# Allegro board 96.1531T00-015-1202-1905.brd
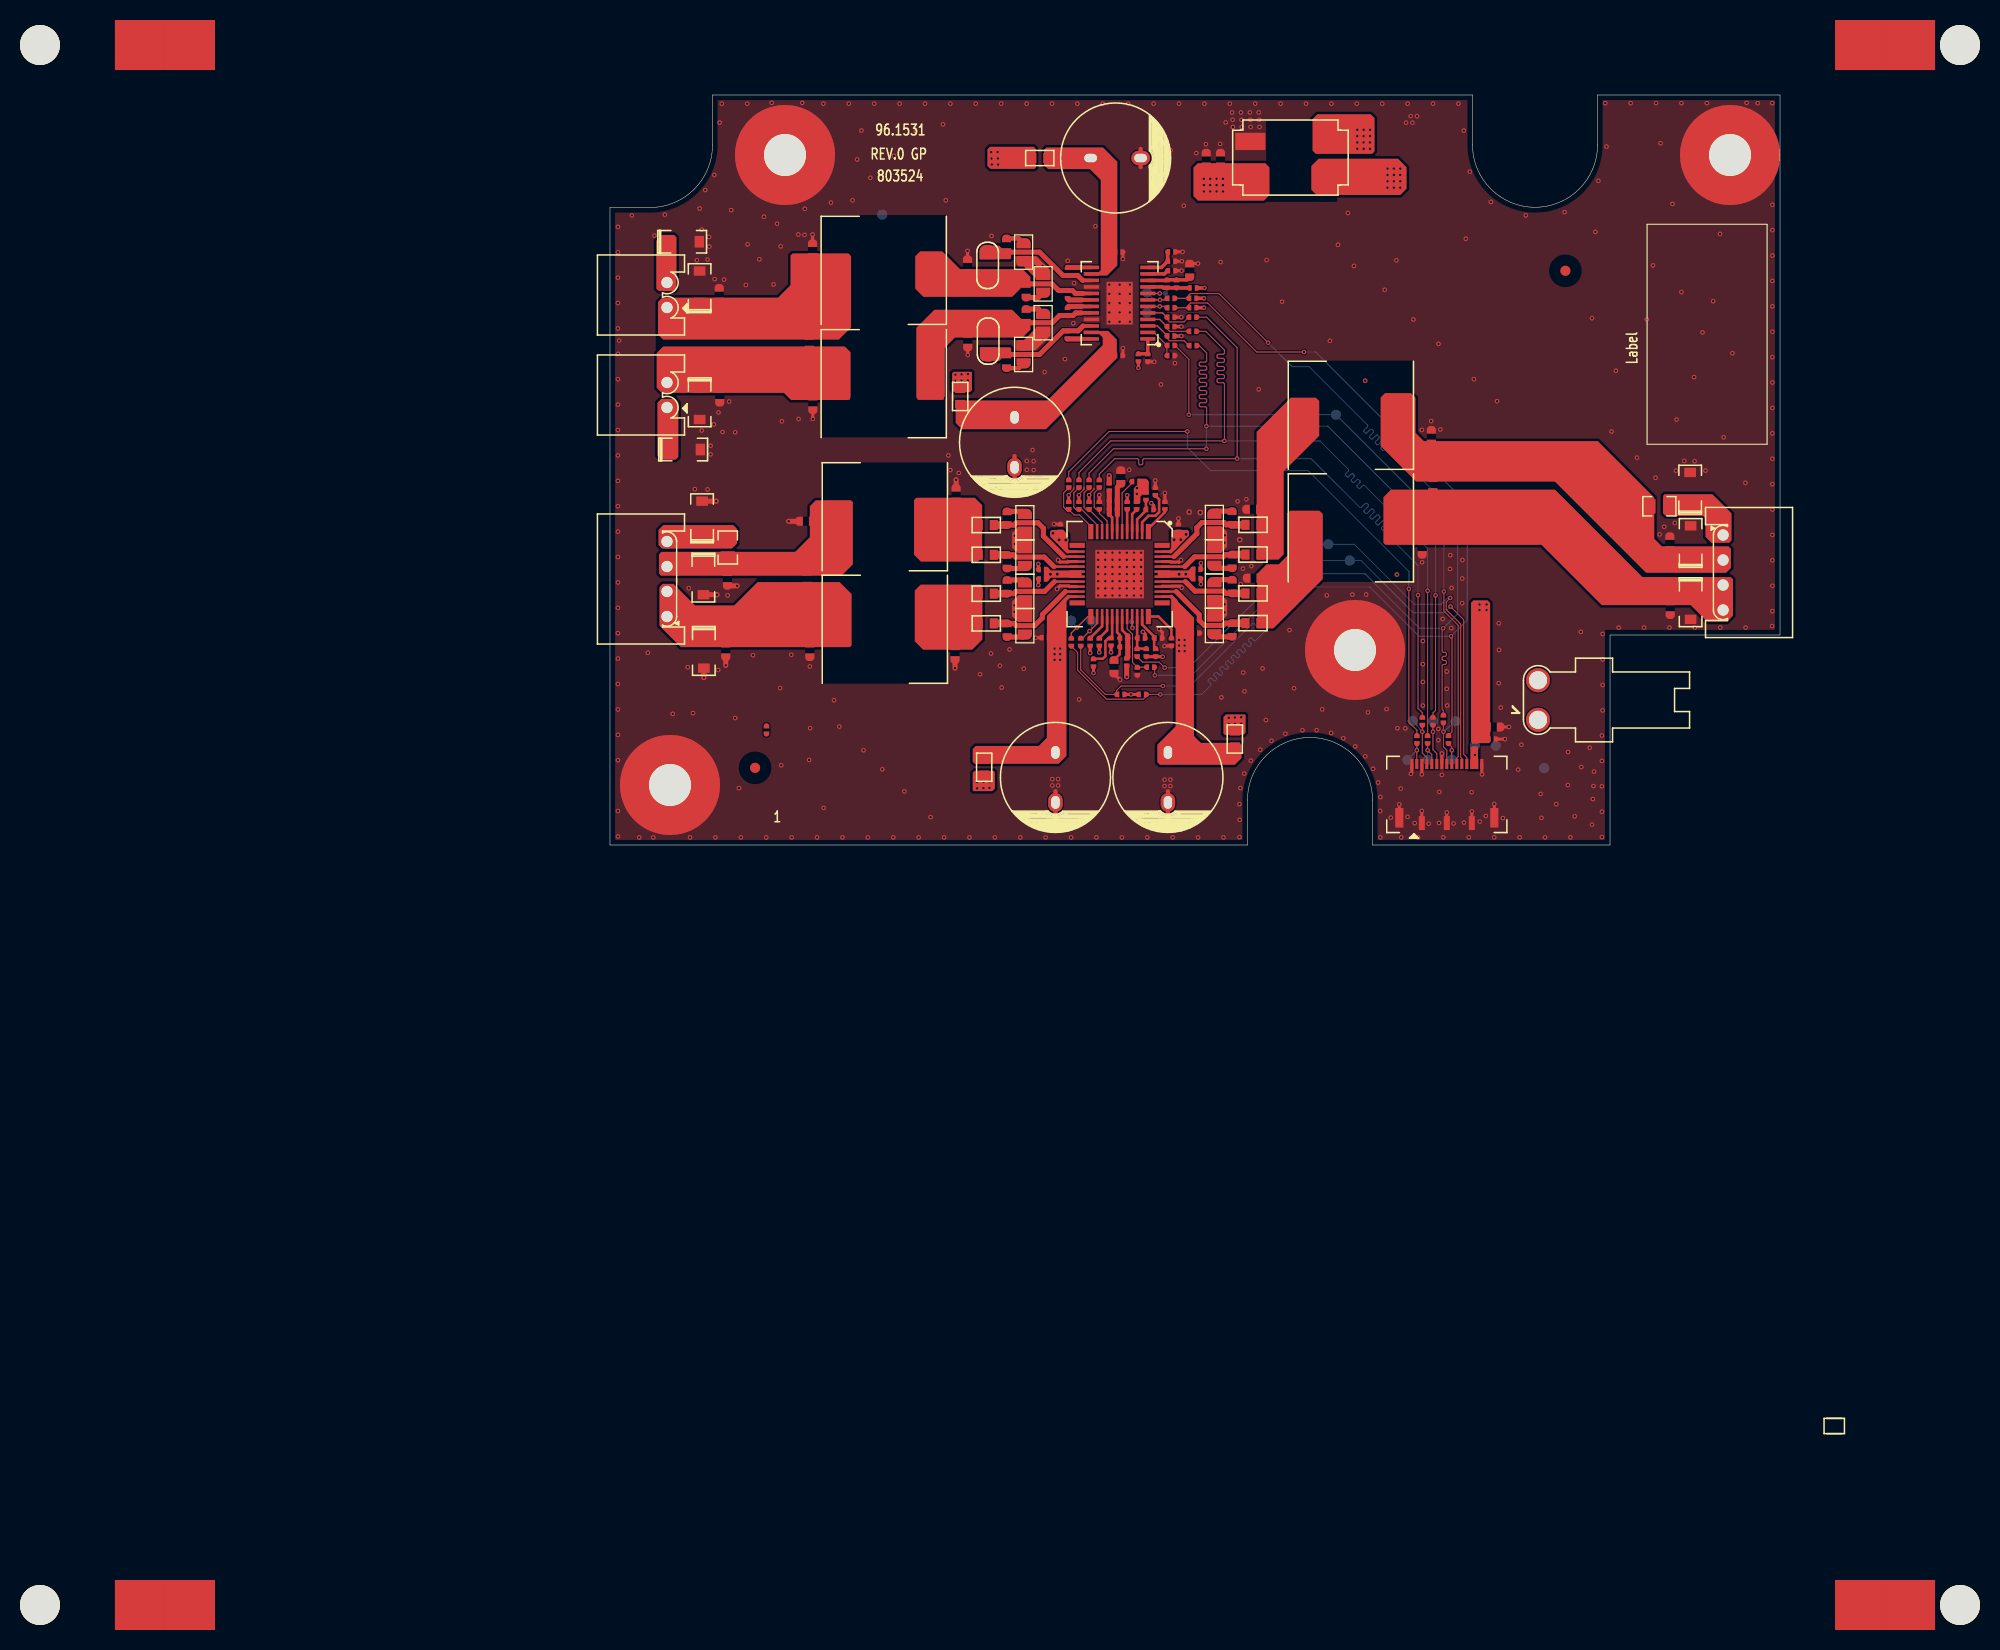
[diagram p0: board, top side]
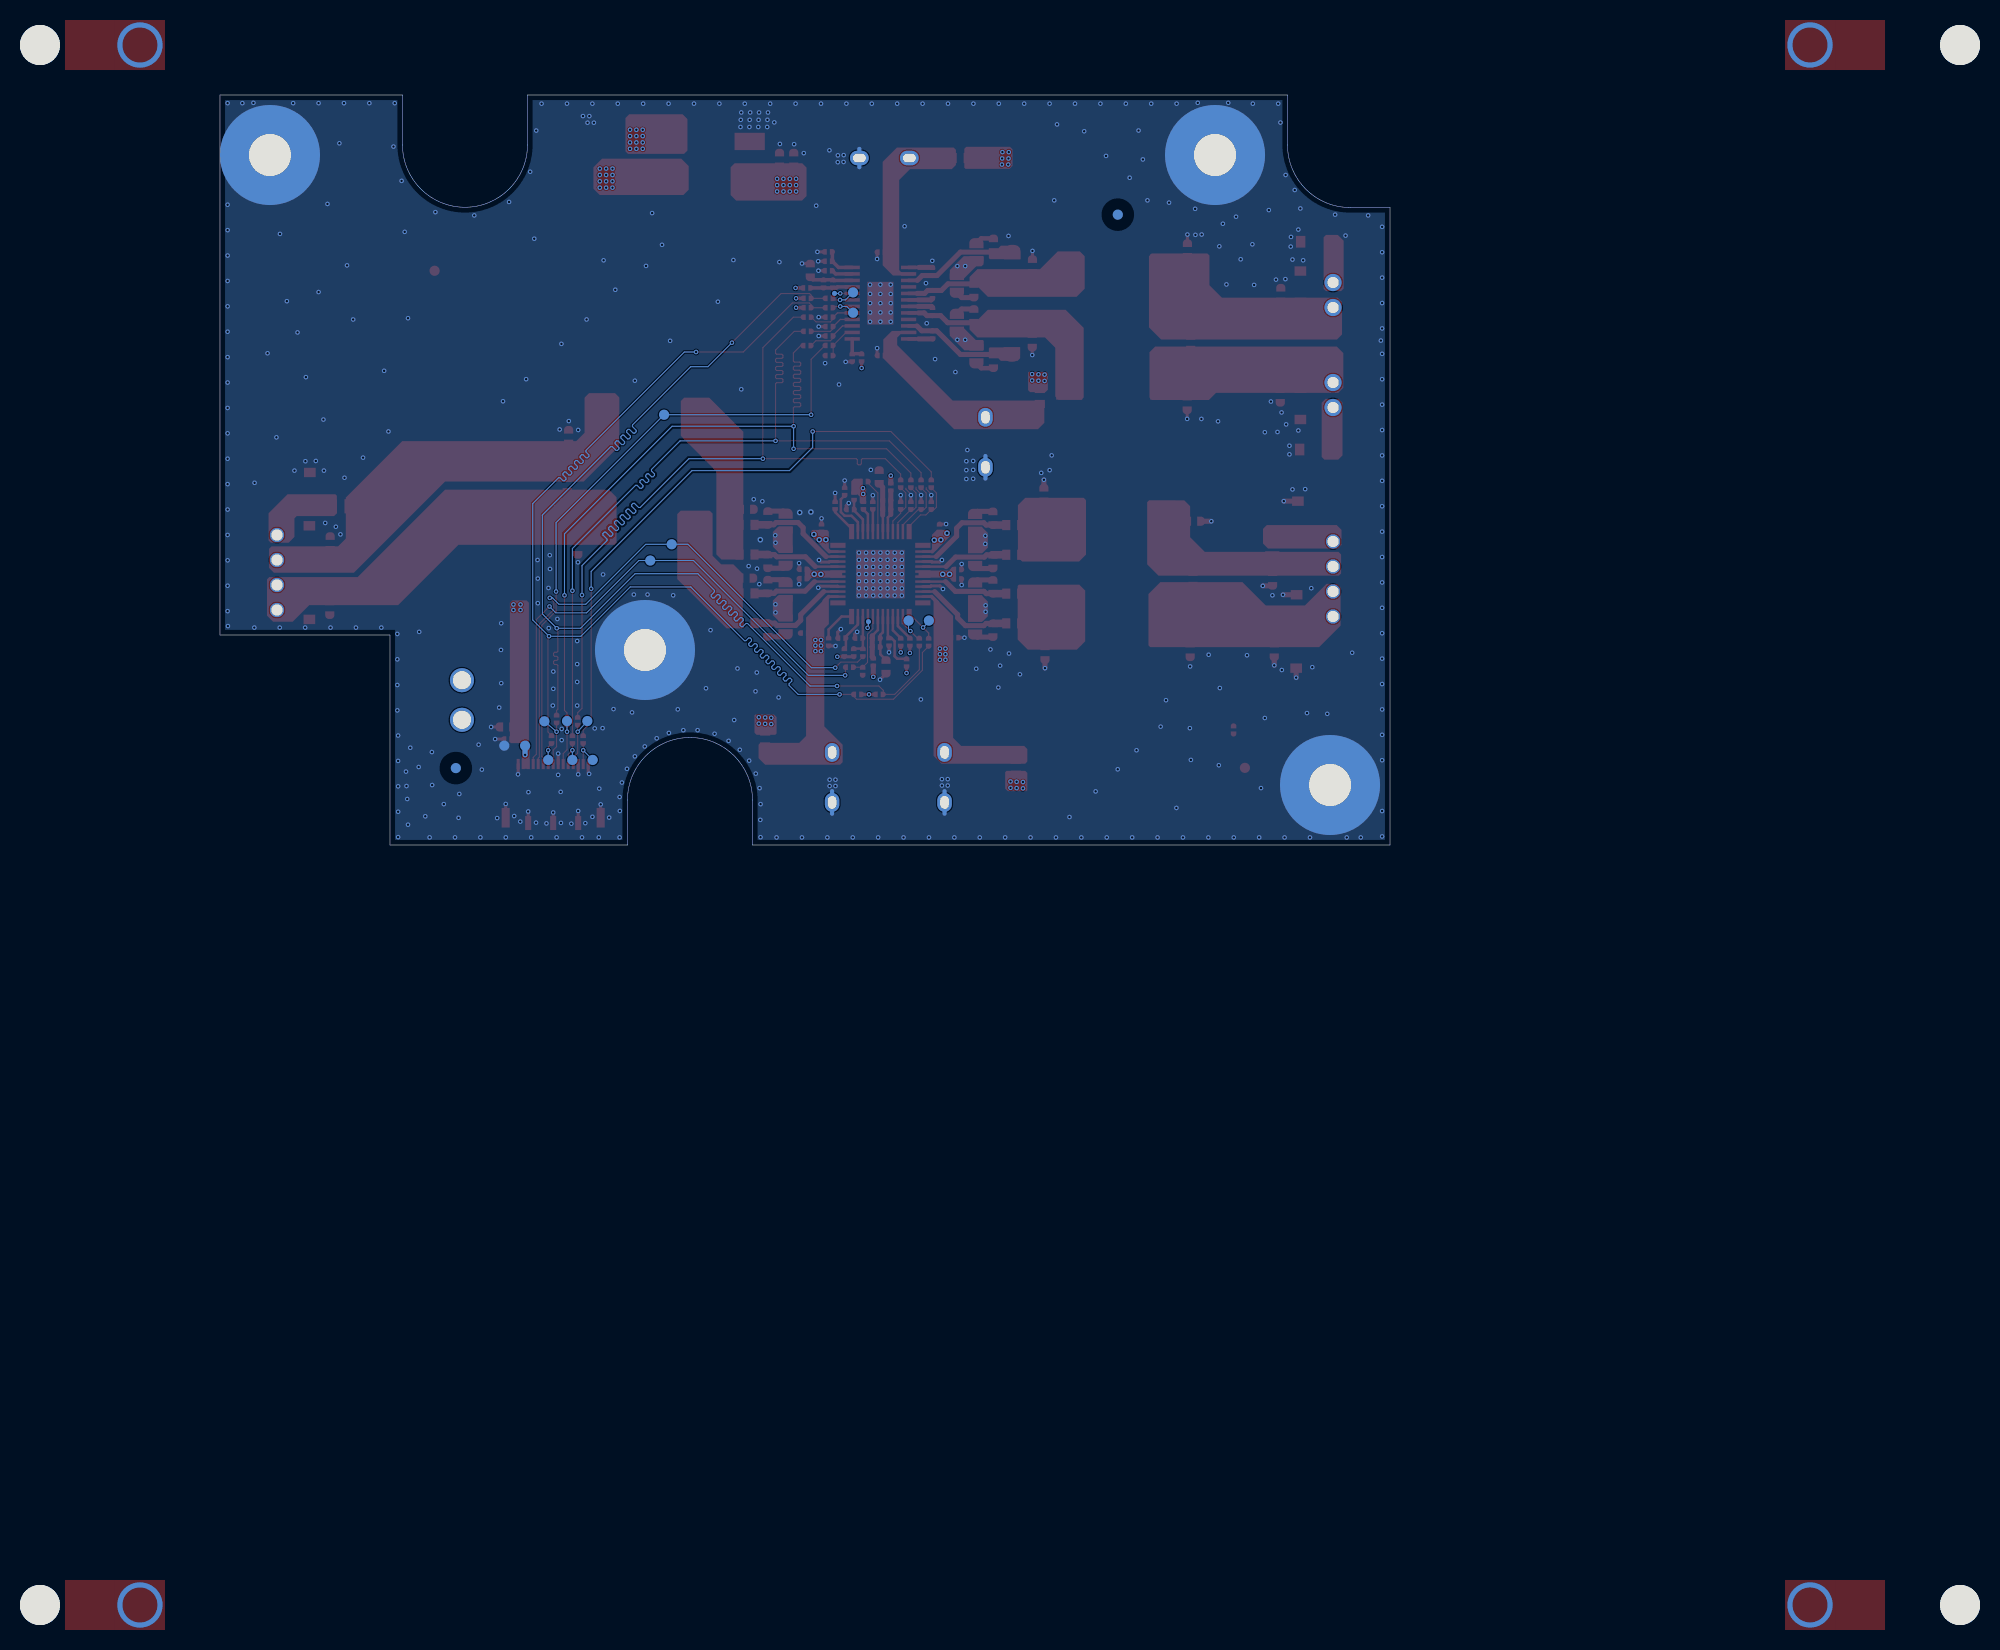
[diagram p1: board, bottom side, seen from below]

Outline 117 x 75 mm; copper layers: TOP, MID1(L2), MID2(L3), BOTTOM. Coordinates in mm from the lower left corner of the outline.
Outline path: 0,63.75 0,0 63.75,0 63.75,4.5 arc(70,10.75) 76.25,4.5 76.25,0 100,0 100,21 117,21 117,75 98.75,75 98.75,70 arc(92.5,63.75) 86.25,70 86.25,75 10.25,75 10.25,70 arc(8.42,65.58) 4,63.75 0,63.75

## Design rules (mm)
net group AD83586B_BCLK: nets AD83586B_BCLK AMP_BCLK BCLK BG5_I2S1_BCLKO
net group AD83586B_DI: nets AD83586B_DI AMP_DI BG5_I2S1_DO DATA
net group AD83586B_LRCK: nets AD83586B_LRCK AMP_LRCK BG5_I2S1_LRCKO LRCK
net group AMP_MSCL: nets AMP_MSCL AMP_SSCL BG5_TW0_SCL SCL
net group AMP_MSDA: nets AMP_MSDA AMP_SSDA BG5_TW0_SDA SDA
net group I2S1: nets BG5_I2S1_MCLK

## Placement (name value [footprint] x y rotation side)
A_D1  SMF36A  [SOD-123G]  7.47 39.55 270 top
A_D2  SMF36A  [SOD-123G]  8.97 44.12 180 top
A_D3  SMF36A  [SOD-123G]  7.37 60.33 270 top
A_D4  SMF36A  [SOD-123G]  8.96 55.83 0 top
A_D5  SMF36A  [SOD-123G]  9.21 32.82 0 top
A_D6  SMF36A  [SOD-123G]  9.34 26.59 180 top
A_D7  SMF36A  [SOD-123G]  9.39 19.25 180 top
A_D8  SMF36A  [SOD-123G]  108.01 35.69 0 top
A_D9  SMF36A  [SOD-123G]  108.06 30.35 0 top
A_D10  SMF36A  [SOD-123G]  108.06 24.13 180 top
BCLK  TP25RD  [ICT040S0]  81.76 8.51 180 bottom
C1218  470pF/50V/X7R/0603  [C-0603S0]  39.66 48.37 180 top
C1219  100nF/50V/X5R  [C-0402S0]  50.88 48.95 270 top
C1220  560uF/35V/DIP  [C-D10_5-5-H22]  40.46 40.27 0 top
C1221  22nF/50V/X7R/0402  [C-0402S0]  45.73 51.02 180 top
C1222  100nF/50V/X7R/0603  [C-0603S0]  20.28 44.16 180 top
C1223  1nF/50V/X7R/0603  [C-0603S0]  10.97 44.91 180 top
C1224  470pF/50V/X7R/0603  [C-0603S0]  41.61 52.91 180 top
C1225  22nF/50V/X7R/0402  [C-0402S0]  45.75 53.35 0 top
C1226  22nF/50V/X7R/0402  [C-0402S0]  45.75 55.05 180 top
C1227  470nF/50V/X7R/0603  [C-0603S0]  19.93 50.23 0 top
C1228  470pF/50V/X7R/0603  [C-0603S0]  41.61 55.43 0 top
C1229  1uF/10V/X5R  [C-0402S0]  55.71 56.11 180 top
C1230  100nF/16V/X5R  [C-0402S0]  56.65 56.11 0 top
C1231  22nF/50V/X7R/0402  [C-0402S0]  45.75 57.35 0 top
C1232  100nF/50V/X7R/0603  [C-0603S0]  20.26 59.5 0 top
C1233  1nF/50V/X7R/0603  [C-0603S0]  10.92 55.04 0 top
C1234  1uF/10V/X5R  [C-0402S0]  56.17 57.43 270 top
C1235  1uF/10V/X5R  [C-0402S0]  56.17 58.37 270 top
C1236  100nF/16V/X5R  [C-0402S0]  56.17 59.32 90 top
C1237  100nF/50V/X5R  [C-0402S0]  50.88 59.29 270 top
C1238  560uF/35V/DIP  [C-D10_5-5-H22]  50.56 68.7 90 top
C1239  470pF/50V/X7R/0603  [C-0603S0]  39.66 59.98 0 top
C1240  1uF/10V/X5R  [C-0402S0]  51.37 19.8 270 top
C1241  100nF/16V/X5R  [C-0402S0]  51.37 20.69 90 top
C1242  470pF/50V/X7R/0603  [C-0603S0]  62.21 21.5 180 top
C1243  470pF/50V/X7R/0603  [C-0603S0]  39.71 21.48 180 top
C1244  560uF/35V/DIP  [C-D10_5-5-H22]  55.79 6.76 0 top
C1245  100nF/50V/X5R  [C-0402S0]  58.56 21.19 270 top
C1246  100nF/50V/X5R  [C-0402S0]  43.52 20.73 90 top
C1247  560uF/35V/DIP  [C-D10_5-5-H22]  44.54 6.76 0 top
C1248  470pF/50V/X7R/0603  [C-0603S0]  39.71 25.82 0 top
C1250  1nF/50V/X7R/0603  [C-0603S0]  106.02 23.67 180 top
C1252  1nF/50V/X7R/0603  [C-0603S0]  11.58 19.46 180 top
C1255  470pF/50V/X7R/0603  [C-0603S0]  62.21 25.85 180 top
C1256  470nF/50V/X7R/0603  [C-0603S0]  19.7 26.62 0 top
C1257  470nF/50V/X7R/0603  [C-0603S0]  82.28 35.99 0 top
C1258  100nF/50V/X5R  [C-0402S0]  58.68 26.63 90 top
C1259  100nF/50V/X5R  [C-0402S0]  43.24 26.61 270 top
C1260  100nF/50V/X5R  [C-0402S0]  58.68 27.57 90 top
C1261  100nF/50V/X5R  [C-0402S0]  43.24 27.55 270 top
C1264  470pF/50V/X7R/0603  [C-0603S0]  62.21 28.36 0 top
C1265  1nF/50V/X7R/0603  [C-0603S0]  105.98 30.21 0 top
C1267  100nF/50V/X5R  [C-0402S0]  56.85 31.69 180 top
C1268  100nF/50V/X5R  [C-0402S0]  45.04 31.69 180 top
C1269  470pF/50V/X7R/0603  [C-0603S0]  39.71 28.34 0 top
C1271  1nF/50V/X7R/0603  [C-0603S0]  11.74 26.6 180 top
C1272  470pF/50V/X7R/0603  [C-0603S0]  39.71 32.68 180 top
C1273  470pF/50V/X7R/0603  [C-0603S0]  62.21 32.7 0 top
C1274  100nF/16V/X5R  [C-0402S0]  50.33 33.57 270 top
C1275  1uF/10V/X5R  [C-0402S0]  50.33 34.46 90 top
C1327  1uF/10V/X5R  [C-0402S0]  53.12 20.69 90 top
C1352  4.7uF/50V/X5R/0805  [C-0805-H1_35]  104.93 33.87 90 top
C1354  4.7uF/50V/X5R/0805  [C-0805-H1_35]  11.78 29.75 0 top
C1357  12pF/50V/NPO  [C-0402S0]  56.09 52.79 270 top
C1358  12pF/50V/NPO  [C-0402S0]  56.09 51.84 270 top
C1359  12pF/50V/NPO  [C-0402S0]  56.09 50.9 270 top
C1360  12pF/50V/NPO  [C-0402S0]  45.87 33.95 180 top
C1361  12pF/50V/NPO  [C-0402S0]  46.89 33.95 180 top
C1362  12pF/50V/NPO  [C-0402S0]  47.91 33.95 180 top
C1363  12pF/50V/NPO  [C-0402S0]  48.93 33.95 180 top
C1380  1uF/50V/0603  [C-0603S0]  59.62 68.56 0 top
C1381  100nF/50V/X7R/0603  [C-0603S0]  61.05 68.56 0 top
C1382  22uF/6.3V/0603  [C-0603S0]  88.38 11.8 90 top
C1383  100nF/16V/X5R  [C-0402S0]  88.21 10.59 90 top
C1384  100nF/50V/X7R/0603  [C-0603S0]  19.59 32.38 90 top
C1385  100nF/50V/X7R/0603  [C-0603S0]  19.98 19.46 180 top
C1386  100nF/50V/X7R/0603  [C-0603S0]  82.13 40.84 0 top
C1387  100nF/50V/X7R/0603  [C-0603S0]  81.21 29.7 180 top
C1388  100nF/50V/X7R/0603  [C-0603S0]  64.29 33.57 90 top
C1389  100nF/50V/X7R/0603  [C-0603S0]  64.34 26.69 90 top
C1390  100nF/50V/X7R/0603  [C-0603S0]  34.61 35.05 0 top
C1391  100nF/50V/X7R/0603  [C-0603S0]  34.5 19.18 180 top
C1392  100nF/50V/X7R/0603  [C-0603S0]  35.75 57.91 0 top
C1393  100nF/50V/X7R/0603  [C-0603S0]  35.77 50.43 180 top
DATA  TP25RD  [ICT040S0]  80.26 12.4 180 bottom
DO  TP25RD  [ICT020]  55.55 55.16 180 bottom
ERROR  TP25RD  [ICT020]  52.15 22.34 0 bottom
FB1  120ohm/3A/0603  [FB-BLM18]  64.3 22.19 90 top
FB2  120ohm/3A/0603  [FB-BLM18]  37.63 22.16 270 top
FB3  120ohm/3A/0603  [FB-BLM18]  37.63 25.13 270 top
FB4  120ohm/3A/0603  [FB-BLM18]  64.3 25.16 90 top
FB5  120ohm/3A/0603  [FB-BLM18]  64.3 29.05 90 top
FB6  120ohm/3A/0603  [FB-BLM18]  37.63 29.02 270 top
FB7  120ohm/3A/0603  [FB-BLM18]  37.63 31.99 270 top
FB8  120ohm/3A/0603  [FB-BLM18]  64.3 32.02 90 top
FID1  NI/FIDUCIAL-MARK  [FIDMS1]  95.54 57.42 0 top
FID2  NI/FIDUCIAL-MARK  [FIDMS1]  14.51 7.72 0 top
FID3  NI/FIDUCIAL-MARK  [FIDMS1]  27.22 63.04 180 bottom
FID4  NI/FIDUCIAL-MARK  [FIDMS1]  93.41 7.69 180 bottom
GND  TP25RD  [ICT040S0]  88.57 9.93 180 bottom
H5  TOOLING HOLE-D=3.2/7mm-PTH  [MPTH165R394I177]  17.5 69 0 top
H6  TOOLING HOLE-D=3.2/7mm-PTH  [MPTH165R394I177]  6 6 0 top
H7  TOOLING HOLE-D=3.2/7mm-PTH  [MPTH165R394I177]  74.5 19.5 0 top
H8  TOOLING HOLE-D=3.2/7mm-PTH  [MPTH165R394I177]  112 69 0 top
J803  S4B-EH(LF)(SN)  [CN-D4X1-2_5RT]  115 27.25 180 top
J804  S4B-EH(LF)(SN)  [CN-D4X1-2_5RT]  2 26.6 0 top
J805  S2B-EH(LF)(SN)  [CN-D2X1-2_5RT]  2 55 0 top
J806  S2B-EH(LF)(SN)  [CN-D2X1-2_5RT]  2 45 0 top
J812  51318-0023L-001  [CN-D2X1-3_96CHD]  98.4 14.5 180 top
J813  502244-1530  [CN-S15X1-0_5A]  83.68 5.07 90 top
L802  120ohm/3A/0603  [FB-BLM18]  35.02 44.85 0 top
L803  10uH/7.8A  [L-S11X10_3-2]  27.38 46.14 90 top
L804  120ohm/1.5A/0402  [L-0402S0]  58.33 55.71 90 top
L805  10uH/7.8A  [L-S11X10_3-2]  27.38 57.46 90 top
L806  120ohm/3A/0603  [FB-BLM18]  42.98 68.7 90 top
L807  120ohm/1.5A/0402  [L-0402S0]  51.67 18.3 0 top
L808  120ohm/3A/0603  [FB-BLM18]  62.48 10.6 180 top
L809  120ohm/3A/0603  [FB-BLM18]  37.42 7.78 180 top
L810  10uH/7.8A  [L-S11X10_3-2]  27.48 21.57 90 top
L811  10uH/7.8A  [L-S11X10_3-2]  74.08 31.72 270 top
L812  10uH/7.8A  [L-S11X10_3-2]  27.48 32.83 90 top
L813  10uH/7.8A  [L-S11X10_3-2]  74.08 42.97 270 top
L814  120ohm/1.5A/0402  [L-0402S0]  49.92 35.8 180 top
L843  1500ohm/3.5A  [L-S9_5X7-4-H7-TEMP]  68.04 68.74 180 top
LRCK  TP25RD  [ICT040S0]  82.3 12.4 180 bottom
MCLK  TP25RD  [ICT040S0]  79.73 8.51 180 bottom
MSCL  TP25RD  [ICT040S0]  53.69 55.26 180 bottom
MSDA  TP25RD  [ICT040S0]  53.69 53.23 180 bottom
NOREF  -  []  111.3 23.5 0 top
NOREF#2  -  []  22.48 37.98 90 top
NOREF#3  -  []  22.68 57.46 0 top
NOREF#4  -  []  49.34 73.8 0 top
NOREF#5  -  []  -62 -71 0 top
NOREF#6  -  []  22.48 26.72 90 top
NOREF#7  -  []  69.08 26.57 0 top
NOREF#8  -  [unnamed#2]  -62 75 270 top
NOREF#9  -  []  -1 32.85 0 top
NOREF#10  -  []  21.98 17.07 90 top
NOREF#11  -  []  47.17 47.94 90 top
NOREF#12  -  []  -20 -16 0 top
NOREF#13  -  []  140 -71 90 top
NOREF#14  -  []  53.34 34.23 0 top
NOREF#15  -  []  68.58 30.22 90 top
NOREF#16  -  []  71.61 -71 90 top
NOREF#17  -  []  61.46 30.59 90 top
NOREF#18  -  []  21.88 52.96 90 top
NOREF#19  -  []  70.84 66.24 0 top
NOREF#20  -  []  69.38 42.97 0 top
NOREF#21  -  []  111.3 26 90 top
NOREF#22  -  []  12.38 62.61 0 top
NOREF#23  -  []  79.08 37.82 90 top
NOREF#24  -  []  0 44.01 0 top
NOREF#25  -  []  63.54 65.24 90 top
NOREF#26  -  []  -1 32.85 0 top
NOREF#27  -  []  0 -14 90 top
NOREF#28  -  []  21.98 28.33 90 top
NOREF#29  -  []  44.36 42.48 0 top
NOREF#30  -  []  63.54 65.24 0 top
NOREF#31  -  []  112 21 0 top
NOREF#32  -  [unnamed#3]  140 -71 270 top
NOREF#33  -  []  22.78 21.57 0 top
NOREF#34  -  []  50.71 22.84 0 top
NOREF#35  -  []  135 -81 90 top
NOREF#36  -  []  46.72 26.84 90 top
NOREF#37  -  []  -62 -41.75 90 top
NOREF#38  -  []  22.38 62.61 90 top
NOREF#39  -  []  135 -81 90 top
NOREF#40  -  []  48.54 22.59 90 top
NOREF#41  -  []  140 -32 90 top
NOREF#42  -  [unnamed#4]  -62 -71 270 top
NOREF#43  -  []  -62 -9.75 90 top
NOREF#44  -  []  48.96 57.39 0 top
NOREF#45  -  []  79.08 26.57 90 top
NOREF#46  -  []  22.68 46.14 0 top
NOREF#47  -  []  22.78 32.83 0 top
NOREF#48  -  []  68.58 41.47 90 top
NOREF#49  -  []  112 21 90 top
NOREF#50  -  []  -62 80 0 top
NOREF#51  -  []  22.38 51.29 90 top
NOREF#52  -  []  122.42 -58.1 0 top
NOREF#53  -  []  54.56 11.86 0 top
NOREF#54  -  []  21.88 41.64 90 top
NOREF#55  -  []  0 -2 0 top
NOREF#56  -  []  12.48 37.98 0 top
NOREF#57  -  []  44.36 42.48 90 top
NOREF#58  -  []  69.08 37.82 0 top
NOREF#59  -  []  54.46 37.59 0 top
NOREF#60  -  []  -62 -71 90 top
NOREF#61  -  []  53.78 53.86 90 top
NOREF#62  -  []  63.29 66.24 0 top
NOREF#63  -  []  63.29 66.24 90 top
NOREF#64  -  []  5 20.35 90 top
NOREF#65  -  []  -62 -41.75 0 top
NOREF#66  -  []  58.1 29.47 90 top
NOREF#67  -  []  -62 5.45 0 top
NOREF#68  -  []  63.75 0 90 top
NOREF#69  -  []  -1 32.85 0 top
NOREF#70  -  []  12.48 26.72 0 top
NOREF#71  -  []  43.32 11.86 0 top
NOREF#72  -  []  5.7 25.35 90 top
NOREF#73  -  []  48.46 24.67 0 top
NOREF#74  -  []  69.38 31.72 0 top
NOREF#75  -  [unnamed#5]  140 75 270 top
NOREF#76  -  []  64.03 67.13 90 top
NOREF#77  -  []  39.23 45.38 0 top
NOREF#78  -  []  12.38 51.29 0 top
NOREF#79  -  []  109.8 21 0 top
NOREF#80  -  []  47.17 47.94 0 top
PD_AD82584F  TP25RD  [ICT040S0]  72.59 43.03 180 bottom
PD_AD83586B  TP25RD  [ICT040S0]  73.97 28.45 180 bottom
R320  4.7K/5%/0402  [R-0402S0]  56.09 48.94 270 top
R2806  0ohm/5%/1206  [R-1206]  37.82 50.39 0 top
R2807  10ohm/5%/0805  [R-0805]  41.36 49.05 0 top
R2808  0ohm/0402  [R-0402S0]  58.27 51.37 90 top
R2809  10ohm/5%/0805  [R-0805]  43.31 52.23 0 top
R2810  0ohm/0402  [R-0402S0]  58.3 49.94 90 top
R2811  0ohm/0402  [R-0402S0]  58.27 52.79 90 top
R2812  0ohm/0402  [R-0402S0]  56.09 53.73 90 top
R2813  0ohm/0402  [R-0402S0]  56.09 54.67 90 top
R2815  10ohm/5%/0805  [R-0805]  43.31 56.11 180 top
R2816  0ohm/0603  [R-0603S0]  57.97 57.46 0 top
R2817  10ohm/5%/0805  [R-0805]  41.36 59.29 180 top
R2818  0ohm/5%/1206  [R-1206]  37.76 57.96 180 top
R2819  0ohm/0603  [R-0603S0]  50.4 17.82 180 top
R2820  10ohm/5%/0805  [R-0805]  60.44 21.96 0 top
R2821  10ohm/5%/0805  [R-0805]  60.44 25.39 0 top
R2822  10ohm/5%/0805  [R-0805]  41.49 21.93 0 top
R2823  10ohm/5%/0805  [R-0805]  41.49 25.36 180 top
R2827  10ohm/5%/0805  [R-0805]  41.49 28.79 180 top
R2829  10ohm/5%/0805  [R-0805]  41.49 32.22 0 top
R2830  10ohm/5%/0805  [R-0805]  60.44 28.82 180 top
R2831  10ohm/5%/0805  [R-0805]  60.44 32.25 180 top
R2832  0ohm/0402  [R-0402S0]  45.87 36.13 180 top
R2833  0ohm/0402  [R-0402S0]  46.89 36.13 180 top
R2834  0ohm/0402  [R-0402S0]  47.91 36.13 180 top
R2835  0ohm/0402  [R-0402S0]  48.93 36.13 180 top
R2837  0ohm/0603  [R-0603S0]  51.08 36.8 0 top
R2886  15K/5%  [R-0402S0]  52.84 48.72 0 top
R2887  15K/5%  [R-0402S0]  53.78 48.72 0 top
R2888  0ohm/0402  [R-0402S0]  56.09 49.96 90 top
R2889  0ohm/0402  [R-0402S0]  47.07 20.28 0 top
R2890  0ohm/0402  [R-0402S0]  46.13 20.28 0 top
R2893  1Mohm  [R-0402S0]  53.63 19.23 180 top
R2894  0ohm/0402  [R-0402S0]  54.82 20.69 90 top
R2895  1K/5%  [R-0402S0]  54.57 19.24 180 top
R2897  1K/5%  [R-0402S0]  48.93 20.28 180 top
R2898  1K/5%  [R-0402S0]  48.01 20.28 180 top
R2899  0ohm/0402  [R-0402S0]  56.14 20.31 0 top
R2901  0ohm/0402  [R-0402S0]  54.53 35.36 180 top
R2902  1K/5%  [R-0402S0]  53.59 34.87 0 top
R2903  1K/5%  [R-0402S0]  52.66 33.95 0 top
R2904  0ohm/0402  [R-0402S0]  51.72 33.95 180 top
R2905  0ohm/0402  [R-0402S0]  55.49 33.95 180 top
R2927  10K/5%  [R-0402S0]  48.35 18.22 180 top
R2928  10K/5%  [R-0402S0]  50.1 20.31 0 top
R2929  0ohm/0402  [R-0402S0]  52.71 19.23 0 top
R2932  10K/5%  [R-0402S0]  58.28 53.73 270 top
R2933  10K/5%  [R-0402S0]  58.28 54.67 270 top
R2968  0ohm/0402  [R-0402S0]  86.48 9.99 0 top
R2970  33/5%/0402  [R-0402S0]  82.3 12.37 0 top
R2971  33/5%/0402  [R-0402S0]  81.76 10.54 0 top
R2972  33/5%/0402  [R-0402S0]  81.23 12.37 0 top
R2974  33/5%/0402  [R-0402S0]  80.69 10.54 0 top
R2976  33/5%/0402  [R-0402S0]  83.85 10.54 0 top
R2977  33/5%/0402  [R-0402S0]  83.34 12.6 0 top
R2980  0ohm/0402  [R-0402S0]  53.98 33.55 90 top
R2981  10K/5%  [R-0402S0]  53.24 15.06 90 top
R2982  10K/5%  [R-0402S0]  51.08 15.06 270 top
R2983  10K/5%  [R-0402S0]  52.58 36.35 90 top
R2984  0ohm/0402  [R-0402S0]  54.05 17.78 90 top
R2985  4.7K/5%/0402  [R-0402S0]  52.73 17.37 180 top
RESET  TP25RD  [ICT040S0]  71.83 30.07 180 bottom
SCL  TP25RD  [ICT040S0]  84.56 12.37 180 bottom
SDA  TP25RD  [ICT040S0]  84.18 8.51 180 bottom
SSCL  TP25RD  [ICT040S0]  48.14 22.44 0 bottom
SSDA  TP25RD  [ICT040S0]  46.11 22.44 0 bottom
U804  AD83586B  [TQFP-48DSH]  50.96 27.09 180 top
U1309  AD82584F  [SSOP-24ESH]  50.96 54.18 0 top
UNK3V3  TP25RD  [ICT040S0]  86.49 9.93 180 bottom
V015  33/5%/0402  [R-0402S0]  15.65 11.51 0 top

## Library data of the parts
A_D1-A_D10 = DIO-TVS-A
BCLK DATA DO ERROR GND LRCK MCLK MSCL MSDA PD_AD82584F PD_AD83586B RESET SCL SDA SSCL SSDA UNK3V3 = TEST_POINT_0
C1218 C1219 C1221-C1228 C1231-C1233 C1237 C1239 C1242 C1243 C1245 C1246 C1248 C1250 C1252 C1255-C1261 C1264 C1265 C1267-C1269 C1271-C1273 C1352 C1354 C1357-C1363 C1380 C1381 C1384-C1393 = CAP
C1220 C1238 C1244 C1247 = CAP AL
C1229 C1234 C1235 C1240 C1275 C1327 = C_0
C1230 C1236 C1241 C1274 C1383 = CAP NP_2
C1382 = CAP NP
FB1-FB8 L802 L804 L806 L807 L809 L814 = BEAD
FID1-FID4 = SCREW-HOLE-1
H5-H8 = TOOLING HOLE-1PIN-NP
J803 J804 = CON4
J805 J806 J812 = CON2X1
J813 = CON15X1-4G_0
L803 L805 L810-L813 = INDUCTOR
L808 = BEAD_0
L843 = CHOKE-4
R320 R2985 = RESISTOR
R2806 R2807 R2809 R2815-R2823 R2827 R2829-R2832 R2837 R2886-R2888 R2893-R2895 R2897-R2899 R2901-R2905 R2927-R2929 R2932 R2933 R2968 R2974 R2980-R2984 V015 = RES
R2808 R2810-R2813 R2833-R2835 R2889 R2890 R2970-R2972 R2976 R2977 = RES: signal model: RES_R-0402S0_0OHM/0402_0ohm/0402
U804 = AD83586B_1
U1309 = AD82584F

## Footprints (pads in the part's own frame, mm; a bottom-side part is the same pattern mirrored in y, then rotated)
C-0402S0
  custom 0.127x0.127 smd: 1(0,-0.406) 2(0,0.406)
C-0603S0
  custom 0.191x0.191 smd: 1(0,-0.686) 2(0,0.686)
C-0805-H1_35
  custom 0.254x0.254 smd: 1(0,-0.889) 2(0,0.889)
C-D10_5-5-H22
  oval 1.448x1.88 hole 0.838x1.27: 1(0,2.5) 2(0,-2.5)
CN-D2X1-2_5RT
  round 1.727 hole 1.118: 1(3.7,-1.25) 2(3.7,1.25)
CN-D2X1-3_96CHD
  round 2.413 hole 1.803: 1(5.6,1.98) 2(5.6,-1.98)
CN-D4X1-2_5RT
  round 1.422 hole 1.118: 1(3.7,-3.75) 2(3.7,-1.25) 3(3.7,1.25) 4(3.7,3.75)
CN-S15X1-0_5A
  rect 1.016x0.305 smd: 1(3.025,3.501) 2(3.025,3.001) 3(3.025,2.501) 4(3.025,2.001) 5(3.025,1.5) 6(3.025,1) 7(3.025,0.5) 8(3.025,0) 9(3.025,-0.5) 10(3.025,-1) 11(3.025,-1.5) 12(3.025,-2.001) 13(3.025,-2.501) 14(3.025,-3.001) 15(3.025,-3.501)
  rect 1.956x0.813 smd: S1(-2.35,4.75) S5(-2.35,-4.75)
  rect 1.397x0.61 smd: S2(-2.879,2.5) S3(-2.879,0) S4(-2.879,-2.5)
FB-BLM18
  rect 1.016x0.813 smd: 1(0,-0.749) 2(0,0.749)
FIDMS1
  round 1.016 smd: 1(0,0)
ICT020
  round 0.508 smd: 1(0,0)
ICT040S0
  round 1.016 smd: 1(0,0)
L-0402S0
  custom 0.127x0.127 smd: 1(0,-0.406) 2(0,0.406)
L-S9_5X7-4-H7-TEMP
  rect 3.023x1.727 smd: 1(4.011,-1.614) 2(4.011,1.614) 3(-4.011,1.614) 4(-4.011,-1.614)
L-S11X10_3-2
  rect 3.2x2.616 smd: 1(0,-4.7) 2(0,4.7)
MPTH165R394I177
  round 10.008 hole 4.191: 1(0,0)
R-0402S0
  custom 0.127x0.127 smd: 1(0,-0.406) 2(0,0.406)
R-0603S0
  custom 0.191x0.191 smd: 1(0,-0.686) 2(0,0.686)
R-0805
  custom 0.254x0.254 smd: 1(0,-0.889) 2(0,0.889)
R-1206
  custom 0.362x0.362 smd: 1(0,-1.333) 2(0,1.333)
SOD-123G
  rect 1.168x0.94 smd: 1(0,-1.568) 2(0,1.568)
SSOP-24ESH
  rect 1.524x0.356 smd: 1(2.819,-3.575) 2(2.819,-2.925) 3(2.819,-2.275) 4(2.819,-1.625) 5(2.819,-0.975) 6(2.819,-0.325) 7(2.819,0.325) 8(2.819,0.975) 9(2.819,1.625) 10(2.819,2.275) 11(2.819,2.925) 12(2.819,3.575) 13(-2.819,3.575) 14(-2.819,2.925) 15(-2.819,2.275) 16(-2.819,1.625) 17(-2.819,0.975) 18(-2.819,0.325) 19(-2.819,-0.325) 20(-2.819,-0.975) 21(-2.819,-1.625) 22(-2.819,-2.275) 23(-2.819,-2.925) 24(-2.819,-3.575)
  rect 2.616x4.267 smd: 25(0,0)
TQFP-48DSH
  rect 0.508x1.524 smd: 1(-2.878,-4.246) 12(2.878,-4.246) 25(2.878,4.246) 36(-2.878,4.246)
  rect 0.254x1.524 smd: 2(-2.25,-4.246) 3(-1.75,-4.246) 4(-1.25,-4.246) 5(-0.75,-4.246) 6(-0.25,-4.246) 7(0.25,-4.246) 8(0.75,-4.246) 9(1.25,-4.246) 10(1.751,-4.246) 11(2.251,-4.246) 26(2.251,4.246) 27(1.751,4.246) 28(1.25,4.246) 29(0.75,4.246) 30(0.25,4.246) 31(-0.25,4.246) 32(-0.75,4.246) 33(-1.25,4.246) 34(-1.75,4.246) 35(-2.25,4.246)
  rect 1.524x0.508 smd: 13(4.246,-2.878) 24(4.246,2.878) 37(-4.246,2.878) 48(-4.246,-2.878)
  rect 1.524x0.254 smd: 14(4.246,-2.25) 15(4.246,-1.75) 16(4.246,-1.25) 17(4.246,-0.75) 18(4.246,-0.25) 19(4.246,0.25) 20(4.246,0.75) 21(4.246,1.25) 22(4.246,1.751) 23(4.246,2.251) 38(-4.246,2.251) 39(-4.246,1.751) 40(-4.246,1.25) 41(-4.246,0.75) 42(-4.246,0.25) 43(-4.246,-0.25) 44(-4.246,-0.75) 45(-4.246,-1.25) 46(-4.246,-1.75) 47(-4.246,-2.25)
  rect 4.851x4.851 smd: 49(0,0)
unnamed#2
  round 1.016 smd: (-5,20) 1(-5,15)
  rect 5.004x5.004 smd: (-5,20) (-5,15)
  round 3.988 hole 3.988 unplated: (-5,5)
unnamed#3
  round 3.988 hole 3.988 unplated: (5,-5)
  rect 5.004x5.004 smd: (5,-10) (5,-15)
  round 1.016 smd: (5,-15.004) 1(5,-10)
unnamed#4
  round 1.016 smd: (5,20) 1(5,15)
  rect 5.004x5.004 smd: (5,20) (5,15)
  round 3.988 hole 3.988 unplated: (5,5)
unnamed#5
  round 3.988 hole 3.988 unplated: (-5,-5)
  rect 5.004x5.004 smd: (-5,-10) (-5,-15)
  round 1.016 smd: (-5,-15) 1(-5,-10)

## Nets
3V3: J813.13 J813.14 R2968.1 UNK3V3.1
GND: A_D1.2 A_D2.2 A_D3.2 A_D4.2 A_D5.2 A_D6.2 A_D7.2 A_D8.2 A_D9.2 A_D10.2 C1219.2 C1220.2(C) C1222.2 C1223.2 C1232.2 C1233.2 C1234.2(B) C1235.2(B) C1236.1 C1237.2 C1238.2(C) C1244.2(C) C1245.2 C1246.2 C1247.2(C) C1250.2 C1252.2 C1258.1 C1259.1 C1260.1 C1261.1 C1265.2 C1267.1 C1268.1 C1271.2 C1327.1(A) C1357.2 C1358.2 C1359.2 C1360.1 C1361.1 C1362.1 C1363.1 C1380.2 C1381.2 C1382.1 C1383.1 C1384.2 C1385.2 C1386.2 C1387.2 C1388.2 C1389.2 C1390.2 C1391.2 C1392.2 C1393.2 GND.1(TP1) H5.1 H6.1 H7.1 H8.1 J813.1 J813.3 J813.7 J813.15 J813.S1 J813.S2 J813.S3 J813.S4 J813.S5 L843.1 R320.2 R2807.2 R2809.1 R2815.1 R2816.2 R2817.2 R2819.2 R2820.2 R2821.1 R2822.2 R2823.2 R2827.1 R2829.1 R2830.1 R2831.2 R2837.2 R2887.1 R2894.1 R2899.1 R2901.1 R2904.1 R2905.1 R2928.1 R2980.1 R2985.2 U804.16(GNDS1) U804.21(GNDS2) U804.40(GNDR) U804.45(GNDL) U804.49(E-PAD) U1309.16(GNDR) U1309.21(GNDL) U1309.25(EPAD)
VDDL: C1219.1 C1220.1(A) L802.1 U1309.23(VDDL)
VDDR: C1237.1 C1238.1(A) L806.1 U1309.14(VDDR)
VDDRA: C1244.1(A) C1245.1 C1258.2 C1260.2 C1267.2 L808.2 U804.38(VDDRA) U804.42(VDDRB) U804.43(VDDLB) U804.47(VDDLA)
VDDSB: C1246.1 C1247.1(A) C1259.2 C1261.2 C1268.2 L809.1 U804.14(VDDSA1) U804.18(VDDSA2) U804.19(VDDSB1) U804.23(VDDSB2)
AD82584_PDN: R320.1 R2888.2 U1309.2(\\P\D\)
AD83586B_BCLK: C1361.2 R2833.2 U804.11(BCLK)
AD83586B_DI: C1363.2 R2835.2 U804.9(SDATA)
AD83586B_LRCK: C1362.2 R2834.2 U804.10(LRCKIN)
AD83586B_MCLK: C1360.2 R2832.2 U804.12(MCLK)
AD83586B_PDN: R2984.2 R2985.1 U804.32(\\P\D\)
AMP_BCLK: C1358.1 R2808.2 U1309.4(BCLK)
AMP_DI: C1357.1 R2811.2 U1309.5(SDATA)
AMP_LRCK: C1359.1 R2810.2 U1309.3(LRCIN)
AMP_MSCL: MSCL.1(TP1) R2813.2 U1309.7(SCL)
AMP_MSDA: MSDA.1(TP1) R2812.2 U1309.6(SDA)
AMP_SSCL: R2889.2 SSCL.1(TP1) U804.26(SCL)
AMP_SSDA: R2890.2 SSDA.1(TP1) U804.25(SDA)
BCLK: BCLK.1(TP1) J813.5 R2971.1
BG5_I2S1_BCLKO: R2808.1 R2833.1 R2971.2
BG5_I2S1_DO: R2811.1 R2835.1 R2972.2
BG5_I2S1_LRCKO: R2810.1 R2834.1 R2970.2
BG5_I2S1_MCLK: R2832.1 R2974.2
BG5_SM_TDO_PCIE_RSTN: J813.11 R2929.1 RESET.1(TP1)
BG5_TW0_SCL: R2813.1 R2889.1 R2933.1 R2977.2 R2982.1
BG5_TW0_SDA: R2812.1 R2890.1 R2932.1 R2976.2 R2981.1
BST_LA: C1221.2 U1309.24(BST_LA)
BST_LB: C1225.2 U1309.19(BST_LB)
BST_RA: C1226.2 U1309.18(BST_RA)
BST_RB: C1231.2 U1309.13(BST_RB)
DATA: DATA.1(TP1) J813.4 R2972.1
LRCK: J813.6 LRCK.1(TP1) R2970.1
MCLK: J813.2 MCLK.1(TP1) R2974.1
MLA: C1218.1 C1221.1 R2806.1 U1309.22(LA)
MLB: C1224.2 C1225.1 C1393.1 L803.1 R2806.2 U1309.20(LB)
MRA: C1226.1 C1228.2 C1392.1 L805.1 R2818.2 U1309.17(RA)
MRB: C1231.1 C1239.1 R2818.1 U1309.15(RB)
PD_AD82584F: J813.10 PD_AD82584F.1(TP1) R2888.1
PD_AD83586B: J813.12 PD_AD83586B.1(TP1) R2984.1
PWR_3V3: C1382.2 C1383.2 L804.1 L807.1 L814.1 R2886.1 R2893.2 R2895.2 R2897.2 R2898.2 R2902.2 R2903.2 R2927.2 R2932.2 R2933.2 R2968.2 R2981.2 R2982.2 R2983.1
PWR_24V: C1380.1 C1381.1 L802.2 L806.2 L808.1 L809.2 L843.2
SAA: C1272.2 FB7.2 U804.15(S1A)
SAB: C1269.2 FB6.2 U804.17(S1B)
SBA: C1243.1 FB2.2 U804.22(S2A)
SBB: C1248.1 FB3.2 U804.20(S2B)
SCL: J813.8 R2977.1 SCL.1(TP1)
SDA: J813.9 R2976.1 SDA.1(TP1)
SLA: C1273.1 FB8.2 U804.46(LA)
SLB: C1264.2 FB5.2 U804.44(LB)
SRA: C1242.1 FB1.2 U804.39(RA)
SRB: C1255.2 FB4.2 U804.41(RB)
N29687767: C1235.1(A) C1236.2 U1309.12(GVDD)
N29687834: C1234.1(A) U1309.11(VREG)
N29687885: C1229.1(A) C1230.2 R2816.1 U1309.10(DGND)
N29687983: C1229.2(B) C1230.1 L804.2 U1309.9(DVDD)
N29689351: C1218.2 R2807.1
N29689362: C1224.1 R2809.2
N29689929: A_D2.1 A_D3.1 C1222.1 C1223.1 C1227.1 J805.2 J806.2 L803.2
N29690216: C1239.2 R2817.1
N29690226: C1228.1 R2815.2
N29690282: A_D1.1 A_D4.1 C1227.2 C1232.1 C1233.1 J805.1 J806.1 L805.2
N29717066: C1274.2 C1275.1(A) R2837.1 U804.7(DGND1)
N29717079: C1274.1 C1275.2(B) L814.2 U804.8(DVDD1)
N29719018: C1240.1(A) C1241.2 R2819.1 U804.30(DGND2)
N29719032: C1240.2(B) C1241.1 L807.2 U804.31(DVDD2)
N29721028: C1242.2 R2820.1
N29721038: C1255.1 R2821.2
N29721066: C1389.1 FB1.1 FB4.1 L811.1
N29721090: A_D10.1 C1250.1 C1257.1 C1387.1 J803.3 J803.4 L811.2
N29721136: C1273.2 R2831.1
N29721154: C1264.1 R2830.2
N29721182: C1388.1 FB5.1 FB8.1 L813.1
N29721210: A_D9.1 C1257.2 C1265.1 C1352.2 C1386.1 J803.2 L813.2
N29736051: A_D6.1 C1256.2 C1271.1 C1354.1 C1384.1 J804.3 L812.2
N29736075: A_D7.1 C1252.1 C1256.1 C1385.1 J804.1 J804.2 L810.2
N29736891: C1248.2 R2823.1
N29736893: C1269.1 R2827.2
N29738065: C1390.1 FB6.1 FB7.1 L812.1
N29738250: C1391.1 FB2.1 FB3.1 L810.1
N29741676: C1243.2 R2822.1
N29741678: C1272.1 R2829.2
N30395079: R2886.2 R2887.2 U1309.1(\\E\R\R\O\R)
N30395618: ERROR.1(TP1) U804.33(\\E\R\R\O\R\)
N30395650: R2901.2 U804.2(MS)
N30396016: R2983.2 U804.6(CLK_OUT)
N30396076: R2902.1 R2980.2 U804.3(\\P\L\L)
N30396158: R2903.1 U804.4(CFG0)
N30396385: R2904.2 U804.5(CFG1)
N30396687: R2898.1 U804.27(SA0)
N30396767: R2897.1 U804.28(SA1)
N30397460: C1327.2(B) R2893.1 R2929.2 U804.34(\\R\E\S\E\T\)
N30397605: R2905.2 U804.1(SDATA1)
N30398199: R2899.2 U804.36(LINEIN)
N30399203: R2894.2 R2895.1 U804.35(LREX)
N30706789: A_D8.1 C1352.1 J803.1
N30708243: A_D5.1 C1354.2 J804.4
N30748963: R2927.1 R2928.2 U804.29(DEF)
N31274082: J812.2 L843.4
N31338205: J812.1 L843.3
N312711240: DO.1(TP1) U1309.8(SDATAO)

Pads without a net: FID1 1; FID2 1; FID3 1; FID4 1; NOREF#8 1; NOREF#32 1; NOREF#42 1; NOREF#75 1; U804 13 24 37 48; V015 1 2

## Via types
v1: diameter 0.457, hole 0.254, TOP to BOTTOM, 658 vias
v2: diameter 0.559, hole 0.305, TOP to BOTTOM, 13 vias

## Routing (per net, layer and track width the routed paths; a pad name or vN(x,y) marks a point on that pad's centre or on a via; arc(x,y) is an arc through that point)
3V3: length 0.9
  BOTTOM w0.508: v1(86.49,9.02) UNK3V3.1
GND: length 82.8
  TOP w0.102: v1(47.91,34.99) 47.91,35.08 48.41,35.59 48.41,35.69 ; v1(45.87,34.99) 45.87,35.08 46.38,35.59 46.38,35.74 ; 47.4,35.79 47.4,35.59 46.89,35.08 v1(46.89,34.99)
  TOP w0.305: C1358.2 v1(57.13,51.84) ; C1383.1 v1(89.48,10.59) ; J813.1 80.18,7.2 v1(80.09,7.11) ; v1(86.18,3.35) 86.18,3.35 J813.S4 ; R2904.1 v1(51.72,34.97) ; R2894.1 55.23,21.28 v1(54.92,21.59) ; v1(57.1,28.5) 56.9,28.3 56.08,28.3 56.04,28.34 U804.45 ; v1(54.13,34.19) 54.38,33.93 R2980.1 ; R2901.1 v1(54.53,36.45) ; U804.40 55.25,25.88 57.02,25.88 v1(57.18,25.73) ; J813.S5 v1(88.43,4.1) ; C1357.2 v1(57.13,52.79) ; C1236.1 v1(57.26,59.32) ; R2899.1 v1(55.45,19.9) ; v1(87.2,7.06) 87.18,7.08 J813.15 ; v1(83.19,9.14) 83.18,9.14 J813.7 ; J813.3 v1(81.18,7.06) ; C1363.1 v1(48.93,34.99) ; v1(44.81,28.5) 45.01,28.3 45.8,28.3 45.84,28.34 U804.16 ; C1362.1 v1(47.91,34.99) ; C1237.2 v1(51.29,58.6) ; C1259.1 v1(42.83,25.99) ; J813.S1 v1(78.93,4.06) ; R2816.2 v1(58.8,58.15) ; v1(53.29,21.31) 53.52,21.07 C1327.1 ; C1235.2 v1(57.18,58.37) ; C1359.2 v1(57.13,50.9) ; v1(42.83,28.1) C1261.1 ; v1(59.09,26.08) C1258.1 ; v1(42.56,20.73) C1246.2 ; R2819.2 v1(51,16.53) ; R2905.1 v1(55.49,35.2) ; R2887.1 v1(54.43,48.32) ; C1360.1 v1(45.87,34.99) ; v1(56.85,32.66) C1267.1 ; C1222.2 v1(20.28,42.61) ; C1361.1 v1(46.89,34.99) ; C1232.2 v1(20.26,61.05) ; C1393.2 v1(35.77,49) ; v1(51.29,49.68) C1219.2 ; J813.S3 v1(83.68,3.25) ; C1260.1 v1(59.09,28.19) ; C1392.2 v1(35.75,59.41) ; J813.S2 v1(81.18,3.4) ; R2928.1 v1(50.1,19.26) ; v1(44.7,25.6) 45.01,25.91 45.9,25.91 45.97,25.84 U804.21 ; C1268.1 v1(44.39,32.09) ; C1234.2 v1(57.16,57.43) ; C1382.1 v1(89.89,11.8)
  TOP w0.406: 53.06,67.79 C1238.2 53.06,69.62 ; 55.79,3.13 C1244.2 55.79,5.39 ; 40.46,36.64 C1220.2 40.46,38.9 ; 44.54,3.13 C1247.2 44.54,5.39
  TOP w0.508: A_D5.2 v1(10.62,34.38) ; C1390.2 v1(34.61,36.53) ; A_D6.2 v1(10.7,25.03) ; C1252.2 v1(11.58,17.96) ; C1384.2 v1(17.87,32.38) ; C1391.2 v1(34.5,17.69) ; C1271.2 v1(12.72,25.91) ; A_D7.2 v1(9.39,16.74)
  MID1(L2) w0.406: 44.54,3.13 C1247.2 44.54,5.39 ; 53.06,67.79 C1238.2 53.06,69.62 ; 40.46,38.9 C1220.2 40.46,36.64 ; 55.79,3.13 C1244.2 55.79,5.39
  MID2(L3) w0.406: 40.46,36.64 C1220.2 40.46,38.9
  BOTTOM w0.406: 44.54,5.39 C1247.2 44.54,3.13 ; 55.79,3.13 C1244.2 55.79,5.39 ; 53.06,67.79 C1238.2 53.06,69.62 ; 40.46,38.9 C1220.2 40.46,36.64
  vias: v1(0.79,61.82) v1(0.79,59.28) v1(0.79,56.74) v1(0.79,54.2) v1(0.79,51.66) v1(0.79,49.12) v1(0.79,46.58) v1(0.79,44.04) v1(0.79,41.5) v1(0.79,38.96) v1(0.79,36.42) v1(0.79,33.88) v1(0.79,31.34) v1(0.79,28.8) v1(0.79,26.26) v1(0.79,23.72) v1(0.79,21.18) v1(0.79,18.64) v1(0.79,16.1) v1(0.79,13.56) v1(0.79,11.02) v1(0.79,8.48) v1(0.79,3.4) v1(0.79,0.86) v1(0.91,50.44) v1(2.19,62.96) v1(2.93,0.76) v1(3.78,19.23) v1(4.33,0.75) v1(4.45,60.94) v1(5.49,63.04) v1(6.27,13.12) v1(7.77,17.78) v1(7.87,25.68) v1(8.01,0.76) v1(8.31,13.19) v1(8.48,35.59) v1(8.69,58.47) v1(8.97,63.65) v1(9.17,61.54) v1(9.17,41.45) v1(9.53,65.5) v1(9.75,58.55) v1(9.75,35.56) v1(9.91,60.81) v1(9.93,59.84) v1(10.06,39.93) v1(10.06,39.07) v1(10.44,67) v1(10.39,42.06) v1(10.46,56.59) v1(10.55,0.76) v1(10.85,43.26) v1(10.82,17.5) v1(10.96,72.25) v1(11.18,74.14) v1(11.25,41.3) v1(11.4,56.54) v1(11.76,24.97) v1(11.91,44.35) v1(12.12,63.49) v1(12.52,41.27) v1(12.52,12.7) v1(12.9,5.69) v1(13.09,0.76) v1(13.59,56.01) v1(13.72,74.14) v1(13.77,60.07) v1(14.3,18.97) v1(14.94,58.57) v1(15.4,62.83) v1(15.63,0.76) v1(16.18,74.22) v1(16.36,56.06) v1(16.71,62.13) v1(17.02,15.7) v1(17.07,59.87) v1(17.12,7.98) v1(17.2,42.37) v1(18.14,19.02) v1(18.17,0.76) v1(18.84,61.05) v1(18.86,42.61) v1(19.23,74.22) v1(19.49,63.62) v1(19.46,61.02) v1(19.91,8.51) v1(19.99,17.86) v1(20.02,11.68) v1(20.71,0.76) v1(21.34,74.14) v1(21.36,3.71) v1(22.1,64.24) v1(22.4,14.48) v1(22.94,11.84) v1(23.25,0.76) v1(23.88,74.14) v1(24.26,64.47) v1(24.71,68.55) v1(25.15,71.45) v1(25.35,9.47) v1(25.79,0.76) v1(26.04,66.73) v1(26.42,74.14) v1(27.23,7.57) v1(28.33,0.76) v1(28.4,68.91) v1(28.96,74.14) v1(29.44,5.36) v1(30.58,71.37) v1(30.87,0.76) v1(31.5,74.14) v1(32.05,2.79) v1(33.3,72.06) v1(33.41,0.76) v1(33.58,64.47) v1(33.83,38.96) v1(34.04,74.14) v1(34.04,37.49) v1(34.87,37.21) v1(35.95,0.76) v1(36.58,74.14) v1(37.01,17.07) v1(38.1,19.15) v1(38.15,60.91) v1(38.49,0.76) v1(38.99,17.93) v1(39.12,74.14) v1(39.17,15.75) v1(39.95,19.56) v1(40.44,23.96) v1(40.44,23.33) v1(40.47,30.93) v1(40.47,30.11) v1(41.03,0.76) v1(41.38,17.63) v1(41.66,74.14) v1(41.68,38.4) v1(41.68,37.52) v1(41.68,36.63) v1(42.27,39.5) v1(42.37,38.38) v1(42.37,37.49) v1(42.37,36.6) v1(42.48,57.89) v1(42.48,50.53) v1(43.26,57.89) v1(43.26,50.53) v1(43.46,47.29) v1(43.57,0.76) v1(44.2,74.14) v1(44.23,6.58) v1(44.23,5.95) v1(44.81,6.58) v1(44.81,5.95) v1(45.49,48.59) v1(45.77,58.42) v1(46.11,0.76) v1(46.33,52.17) v1(46.41,56.18) v1(46.74,74.14) v1(46.91,14.55) v1(48.54,61.87) v1(48.65,0.76) v1(48.82,29.24) v1(48.82,28.52) v1(48.82,27.81) v1(48.82,27.09) v1(48.82,26.38) v1(48.82,25.66) v1(48.82,24.94) v1(49.28,74.14) v1(49.53,29.24) v1(49.53,28.52) v1(49.53,27.81) v1(49.53,27.09) v1(49.53,26.38) v1(49.53,25.66) v1(49.53,24.94) v1(49.93,56.04) v1(49.93,55.11) v1(49.93,54.18) v1(49.93,53.26) v1(49.93,52.33) v1(50.25,29.24) v1(50.25,28.52) v1(50.25,27.81) v1(50.25,27.09) v1(50.25,26.38) v1(50.25,25.66) v1(50.25,24.94) v1(50.96,56.04) v1(50.96,55.11) v1(50.96,54.18) v1(50.96,53.26) v1(50.96,52.33) v1(50.96,29.24) v1(50.96,28.52) v1(50.96,27.81) v1(50.96,27.09) v1(50.96,26.38) v1(50.96,25.66) v1(50.96,24.94) v1(51.19,0.76) v1(51.68,29.24) v1(51.68,28.52) v1(51.68,27.81) v1(51.68,27.09) v1(51.68,26.38) v1(51.68,25.66) v1(51.68,24.94) v1(51.82,74.14) v1(51.92,37.52) v1(51.99,56.04) v1(51.99,55.11) v1(51.99,54.18) v1(51.99,53.26) v1(51.99,52.33) v1(52.39,29.24) v1(52.39,28.52) v1(52.39,27.81) v1(52.39,27.09) v1(52.39,26.38) v1(52.39,25.66) v1(52.39,24.94) v1(53.11,29.24) v1(53.11,28.52) v1(53.11,27.81) v1(53.11,27.09) v1(53.11,26.38) v1(53.11,25.66) v1(53.11,24.94) v1(53.73,0.76) v1(54.36,74.14) v1(54.63,68.99) v1(54.64,68.31) v1(55.09,46.05) v1(55.21,68.97) v1(55.23,68.28) v1(55.45,6.53) v1(55.45,5.9) v1(56.04,6.53) v1(56.04,5.9) v1(56.06,69.47) v1(56.27,0.76) v1(56.49,48.18) v1(56.9,74.14) v1(57.38,63.93) v1(58.62,69.19) v1(58.81,0.76) v1(59.44,74.14) v1(59.59,70.08) v1(61.01,70.1) v1(61.06,58.29) v1(61.14,14.76) v1(61.35,0.76) v1(61.45,30.23) v1(61.47,30.97) v1(61.45,24.07) v1(61.45,23.26) v1(61.57,72.26) v1(61.98,74.14) v1(62.2,73.25) v1(62.26,72.52) v1(62.28,71.81) v1(62.76,34.37) v1(62.94,4.09) v1(62.95,0.78) v1(63.04,5.69) v1(62.97,2.51) v1(63.09,73.25) v1(63.14,72.52) v1(63.07,26.09) v1(63.17,71.81) v1(63.3,27.64) v1(63.32,17.25) v1(63.45,15.37) v1(63.42,7.14) v1(63.63,34.57) v1(63.98,73.25) v1(64.03,72.52) v1(64.06,71.81) v1(64.14,27.89) v1(64.08,8.43) v1(64.52,74.14) v1(64.87,73.25) v1(64.92,72.52) v1(64.95,71.81) v1(64.87,45.57) v1(65.02,9.53) v1(65.25,17.65) v1(65.58,12.5) v1(65.66,58.5) v1(66.14,10.41) v1(67.06,74.14) v1(67.21,54.33) v1(67.54,11.13) v1(67.94,21.49) v1(68.4,15.67) v1(69.24,11.48) v1(69.6,74.14) v1(70.66,11.48) v1(71.22,13.56) v1(71.68,24.97) v1(71.98,50.42) v1(72.14,74.14) v1(72.11,11.2) v1(72.8,60.02) v1(73.33,10.67) v1(73.79,63.2) v1(74.24,25.04) v1(74.4,57.91) v1(74.52,9.86) v1(74.68,74.14) v1(75.51,46.43) v1(75.51,8.86) v1(75.62,25.04) v1(75.79,13.26) v1(76.3,7.62) v1(76.81,6.25) v1(77.04,4.8) v1(77.01,3.4) v1(77.04,0.76) v1(77.22,74.14) v1(77.47,55.52) v1(77.65,13.59) v1(78.08,2.74) v1(78.64,58.47) v1(78.69,27.05) v1(78.74,11.68) v1(79.07,5.64) v1(79.12,0.76) v1(79.53,11.66) v1(79.61,72.23) v1(79.76,74.14) v1(79.76,2.82) v1(80.07,72.89) v1(80.24,72.23) v1(80.34,52.55) v1(80.47,2.18) v1(80.7,72.89) v1(80.8,0.76) v1(81.18,41.5) v1(81.2,28.27) v1(81.28,20.4) v1(81.28,18.08) v1(81.28,16.31) v1(81.28,13.94) v1(81.86,2.13) v1(82.12,42.39) v1(82.3,74.14) v1(82.83,11.61) v1(82.83,10.49) v1(82.85,50.11) v1(82.93,5.31) v1(82.91,2.21) v1(83.03,41.55) v1(83.19,7.01) v1(83.26,22.61) v1(83.34,0.76) v1(83.67,17.35) v1(83.67,15.62) v1(83.72,13.94) v1(84.02,28.98) v1(84,27.61) v1(84.12,21.69) v1(84.15,25.7) v1(84.35,2.16) v1(84.84,74.14) v1(85.24,28.5) v1(85.22,26.64) v1(85.22,24.18) v1(85.37,71.44) v1(85.39,2.24) v1(85.57,60.63) v1(85.88,0.76) v1(85.98,67.33) v1(86.16,5.28) v1(86.39,46.58) v1(86.97,2.34) v1(87.58,2.9) v1(88.09,64.31) v1(88.42,0.76) v1(88.7,44.37) v1(88.87,22.17) v1(88.9,19.51) v1(88.87,16.18) v1(89.08,13.74) v1(89.28,2.69) v1(90.82,7.54) v1(90.96,0.76) v1(91.14,10.03) v1(91.57,62.96) v1(93.07,5.11) v1(93.14,2.72) v1(93.5,0.76) v1(94.61,4.09) v1(95.46,63.29) v1(95.81,9.3) v1(95.78,5.99) v1(96.04,0.76) v1(96.47,2.87) v1(97.08,21.31) v1(97.13,7.8) v1(97.97,9.73) v1(98.2,52.68) v1(98.2,2.03) v1(98.35,5.89) v1(98.27,4.6) v1(98.4,7.34) v1(98.53,61.32) v1(98.84,66.41) v1(99.19,10.95) v1(99.19,8.41) v1(99.19,5.87) v1(99.19,3.33) v1(99.19,0.79) v1(99.26,21.11) v1(99.26,18.57) v1(99.26,16) v1(99.26,13.46) v1(99.52,74.19) v1(99.65,69.84) v1(100.15,41.35) v1(100.58,47.42) v1(100.86,21.74) v1(102.06,74.19) v1(102.69,38.73) v1(103.4,21.74) v1(103.68,52.55) v1(104.29,57.96) v1(104.55,36.73) v1(104.6,74.19) v1(104.95,31.06) v1(105.06,70.17) v1(105.41,31.83) v1(105.94,21.74) v1(106.25,64.11) v1(106.48,32.21) v1(106.6,37.44) v1(106.65,42.55) v1(107.14,74.19) v1(107.14,55.3) v1(107.42,38.4) v1(108.41,46.79) v1(108.46,38.38) v1(108.48,21.74) v1(109.25,51.26) v1(109.55,37.44) v1(109.68,74.19) v1(110.31,54.38) v1(111,61.11) v1(111.02,21.74) v1(111.35,40.77) v1(112.24,49.17) v1(113.54,36.22) v1(113.56,21.74) v1(113.65,74.22) v1(114.76,74.19) v1(116.24,74.19) v1(116.24,64.03) v1(116.24,61.49) v1(116.24,58.95) v1(116.24,56.41) v1(116.24,53.87) v1(116.24,51.33) v1(116.24,48.79) v1(116.24,46.25) v1(116.24,43.71) v1(116.24,41.17) v1(116.24,38.63) v1(116.24,36.09) v1(116.24,33.55) v1(116.24,31.01) v1(116.24,28.47) v1(116.24,25.93) v1(116.24,23.39) v1(116.2,21.89) v2(57.91,33.3) v2(59.03,33.25) v2(62.97,30.53)
VDDRA: length 3.2
  TOP w0.254: 56.13,24.84 U804.38 ; 56.06,29.34 U804.47
  TOP w0.381: 56.65,29.94 56.06,29.34 ; 56.57,24.39 56.13,24.84
  vias: v1(56.9,20.5) v1(56.9,19.94) v1(56.9,19.39) v1(57.46,20.5) v1(57.46,19.94) v1(57.46,19.39) v2(56.41,30.53) v2(56.91,27.07) v2(57.07,30.53) v2(57.61,31.06) v2(57.58,27.08)
VDDSB: length 3.2
  TOP w0.254: 45.84,24.84 U804.23 ; U804.14 45.78,29.34
  TOP w0.381: 45.27,24.27 45.84,24.84 ; 45.78,29.34 45.37,29.75
  vias: v1(44.46,19.64) v1(44.46,19.08) v1(44.46,18.52) v1(45.02,19.64) v1(45.02,19.08) v1(45.02,18.52) v2(44.04,27.08) v2(44.3,31.18) v2(44.73,27.08) v2(44.91,30.52) v2(45.57,30.49)
AD82584_PDN: length 3.5
  TOP w0.102: U1309.2 54.38,51.26 R2888.2 R320.1
AD83586B_BCLK: length 5.9
  TOP w0.102: R2833.2 46.38,35.21 46.38,33.77 46.61,33.54 C1361.2 47.18,33.54 48.71,32.01 U804.11
AD83586B_DI: length 5.3
  TOP w0.102: U804.9 49.71,32.4 48.93,33.18 C1363.2 48.64,33.54 48.42,33.77 48.42,35.21 R2835.2
AD83586B_LRCK: length 5.5
  TOP w0.102: R2834.2 47.4,35.21 47.4,33.77 47.62,33.54 C1362.2 49.21,32.24 U804.10
AD83586B_MCLK: length 6.2
  TOP w0.102: R2832.2 45.36,35.21 45.36,33.77 45.6,33.54 C1360.2 46.41,33.01 46.95,33.01 48.08,31.88 U804.12
AD83586B_PDN: length 6.4
  TOP w0.102: R2984.2 R2985.1 52.25,18.26 52.25,21.08 51.71,21.62 U804.32
AMP_BCLK: length 4.7
  TOP w0.102: R2808.2 55.96,51.37 55.68,51.65 C1358.1
  TOP w0.127: C1358.1 54.97,52.56 U1309.4
AMP_DI: length 4.8
  TOP w0.102: R2811.2 57.39,52.31 55.96,52.31 55.68,52.59 C1357.1
  TOP w0.127: C1357.1 55.26,53.21 U1309.5
AMP_LRCK: length 5.1
  TOP w0.102: C1359.1 55.68,50.69 55.95,50.43 57.41,50.43 R2810.2
  TOP w0.127: U1309.3 54.74,51.91 55.68,50.97 C1359.1
AMP_MSCL: length 3.6
  TOP w0.127: R2813.2 55.53,54.51 v1(55,54.51) U1309.7
  BOTTOM w0.102: MSCL.1 54.44,54.51 v1(55,54.51)
AMP_MSDA: length 3.5
  TOP w0.127: R2812.2 55.55,53.86 v1(54.97,53.86) U1309.6
  BOTTOM w0.102: v1(54.97,53.86) 54.32,53.86 MSDA.1
AMP_SSCL: length 4.1
  TOP w0.127: U804.26 48.71,22.15 v1(47.96,21.39) 47.25,20.69 R2889.2
  BOTTOM w0.102: v1(47.96,21.39) 48.14,21.58 SSCL.1
AMP_SSDA: length 4.1
  TOP w0.127: R2890.2 46.13,21.19 v1(46.69,21.75) 47.78,22.84 U804.25
  BOTTOM w0.102: SSDA.1 46.11,22.33 v1(46.69,21.75)
BCLK: length 3.2
  TOP w0.102: J813.5 82.18,9.05 v1(81.76,9.47) R2971.1
  BOTTOM w0.102: BCLK.1 v1(81.76,9.47)
BG5_I2S1_BCLKO: length 80.7
  TOP w0.102: R2833.1 46.89,37.24 50.06,40.41 v1(61.44,40.41) 61.44,46.13 61.34,46.23 60.81,46.23 60.71,46.33 60.71,46.54 60.81,46.64 61.34,46.64 61.44,46.74 61.44,46.94 61.34,47.04 60.81,47.04 60.71,47.14 60.71,47.35 60.81,47.45 61.34,47.45 61.44,47.55 61.44,47.75 61.34,47.86 60.81,47.86 60.71,47.96 60.71,48.16 60.81,48.26 61.34,48.26 61.44,48.36 61.44,48.57 61.34,48.67 60.81,48.67 60.71,48.77 60.71,48.97 60.81,49.08 61.34,49.08 61.44,49.18 61.44,49.5 59.57,51.37 R2808.1 ; R2971.2 v1(81.76,25.43)
  BOTTOM w0.102: v1(61.44,40.41) 70.99,40.41 73.85,37.55 73.85,37.41 73.55,37.11 73.55,36.96 73.7,36.82 73.84,36.82 74.14,37.12 74.28,37.12 74.43,36.98 74.43,36.83 74.13,36.53 74.13,36.39 74.27,36.24 74.41,36.24 74.72,36.55 74.86,36.55 75,36.4 75,36.26 74.7,35.96 74.7,35.81 74.85,35.67 74.99,35.67 75.29,35.97 75.43,35.97 81.76,29.65 v1(81.76,25.43)
BG5_I2S1_DO: length 78.3
  TOP w0.102: R2835.1 48.93,37.09 50.47,38.63 52.76,38.63 52.87,38.53 52.87,38.13 52.97,38.02 53.17,38.02 53.27,38.13 53.27,38.53 53.37,38.63 v1(62.71,38.63) 62.71,49.73 59.66,52.79 R2811.1 ; v1(80.8,24.99) 80.8,13.67 81.23,13.23 R2972.2
  BOTTOM w0.102: v1(80.8,24.99) 80.8,27.94 78.29,30.44 78.29,30.59 78.71,31 78.71,31.15 78.56,31.29 78.42,31.29 78.01,30.87 77.86,30.87 77.72,31.02 77.72,31.16 78.13,31.58 78.13,31.72 77.99,31.87 77.85,31.87 77.43,31.45 77.29,31.45 77.14,31.59 77.14,31.74 77.56,32.15 77.56,32.3 77.41,32.44 77.27,32.44 76.86,32.03 76.71,32.03 76.57,32.17 76.57,32.31 76.98,32.73 76.98,32.87 76.84,33.02 76.7,33.02 76.28,32.6 76.14,32.6 75.99,32.74 75.99,32.89 76.41,33.3 76.41,33.45 76.26,33.59 76.12,33.59 75.71,33.18 75.56,33.18 75.42,33.32 75.42,33.46 75.83,33.88 75.83,34.02 75.69,34.17 75.55,34.17 75.13,33.75 74.99,33.75 70.1,38.63 v1(62.71,38.63)
BG5_I2S1_LRCKO: length 77.5
  TOP w0.102: R2834.1 47.91,37.19 50.34,39.62 v1(59.64,39.62) ; R2810.1 58.92,49.94 59.66,49.2 59.66,48.39 59.56,48.29 59.03,48.29 58.93,48.19 58.93,47.99 59.03,47.89 59.56,47.89 59.66,47.78 59.66,47.58 59.56,47.48 59.03,47.48 58.93,47.38 58.93,47.18 59.03,47.07 59.56,47.07 59.66,46.97 59.66,46.77 59.56,46.67 59.03,46.67 58.93,46.57 58.93,46.36 59.03,46.26 59.56,46.26 59.66,46.16 59.66,45.96 59.56,45.85 59.03,45.85 58.93,45.75 58.93,45.55 59.03,45.45 59.56,45.45 59.66,45.35 59.66,45.14 59.56,45.04 59.03,45.04 58.93,44.94 58.93,44.74 59.03,44.64 59.56,44.64 59.66,44.53 59.66,44.33 59.56,44.23 59.03,44.23 58.93,44.13 58.93,43.92 59.03,43.82 59.56,43.82 59.66,43.72 59.66,41.9 v1(59.64,41.88) ; R2970.2 82.3,13.21 82.55,13.46 v1(82.55,24.97)
  BOTTOM w0.102: v1(59.64,39.62) v1(59.64,41.88) 71.79,41.88 82.55,31.11 v1(82.55,24.97)
BG5_I2S1_MCLK: length 59.9
  TOP w0.102: R2974.2 80.69,11.49 79.88,12.29 v1(79.88,25.63) ; v1(57.73,41.35) 49.91,41.35 45.87,37.31 R2832.1
  BOTTOM w0.102: v1(57.73,41.35) 57.73,39.75 60.05,37.44 69.8,37.44 79.88,27.36 v1(79.88,25.63)
BG5_SM_TDO_PCIE_RSTN: length 57.1
  TOP w0.102: R2929.1 53.25,18.29 54.91,18.29 v1(55.47,17.73) ; J813.11 85.18,8.67 85.06,8.79 85.06,22.1 83.62,23.55 83.62,24.31 v1(84.02,24.71)
  BOTTOM w0.102: v1(55.47,17.73) 57.86,17.73 70.21,30.07 RESET.1 74.42,30.07 80.42,24.08 83.11,24.08 83.74,24.71 v1(84.02,24.71)
BG5_TW0_SCL: length 118.3
  TOP w0.102: v1(55.3,15.9) 51.1,15.9 50.67,15.47 R2982.1 49.53,15.06 47.07,17.52 R2889.1 ; R2813.1 57.87,54.67 R2933.1 57.87,54.98 58.04,55.14 60.89,55.14 v1(65.8,50.23) ; R2977.2 83.34,13.46 83.21,13.59 83.21,17.95 83.31,18.05 83.54,18.05 83.64,18.16 83.64,18.36 83.54,18.46 83.31,18.46 83.21,18.56 83.21,18.77 83.31,18.87 83.54,18.87 83.64,18.97 83.64,19.17 83.54,19.27 83.31,19.27 83.21,19.37 83.21,21.56 v1(83.32,21.68)
  BOTTOM w0.102: v1(65.8,50.23) 68.21,47.83 69.93,47.83 75.76,42 75.76,41.85 75.38,41.47 75.38,41.33 75.53,41.19 75.67,41.19 76.05,41.56 76.19,41.56 76.33,41.42 76.33,41.28 75.96,40.9 75.96,40.76 76.1,40.61 76.24,40.61 76.62,40.99 76.77,40.99 76.91,40.85 76.91,40.7 76.53,40.32 76.53,40.18 76.68,40.04 76.82,40.04 77.2,40.41 77.34,40.41 77.48,40.27 77.48,40.13 77.11,39.75 77.11,39.61 77.25,39.46 77.39,39.46 77.77,39.84 77.92,39.84 84.76,32.99 84.76,23.11 v1(83.32,21.68) 80.94,21.68 75.49,27.13 69.22,27.13 67.55,25.47 67.55,25.32 67.88,25 67.88,24.85 67.74,24.71 67.59,24.71 67.27,25.04 67.12,25.04 66.98,24.89 66.98,24.75 67.31,24.42 67.31,24.28 67.16,24.13 67.02,24.13 66.69,24.46 66.55,24.46 66.4,24.32 66.4,24.17 66.73,23.85 66.73,23.7 66.59,23.56 66.44,23.56 66.12,23.88 65.97,23.88 65.83,23.74 65.83,23.6 66.16,23.27 66.16,23.13 66.01,22.98 65.87,22.98 65.54,23.31 65.4,23.31 65.25,23.17 65.25,23.02 65.58,22.7 65.58,22.55 65.44,22.41 65.29,22.41 64.97,22.73 64.82,22.73 64.68,22.59 64.68,22.45 65,22.12 65,21.98 64.86,21.83 64.72,21.83 64.39,22.16 64.25,22.16 57.99,15.9 v1(55.3,15.9)
BG5_TW0_SDA: length 122.6
  TOP w0.102: v1(55.04,15.06) R2981.1 53.64,14.88 53.34,14.58 49.66,14.58 46.76,17.48 46.76,19.24 R2890.1 ; R2812.1 57.87,53.73 R2932.1 57.87,54.01 58.06,54.2 59.77,54.2 64.67,49.3 v1(69.39,49.3) ; R2976.2 84.2,11.3 84.2,20.78 v1(84.1,20.88)
  BOTTOM w0.102: v1(55.04,15.06) 59.18,15.06 60.09,15.97 60.09,16.12 59.82,16.39 59.82,16.54 59.96,16.68 60.11,16.68 60.38,16.41 60.53,16.41 60.67,16.55 60.67,16.69 60.39,16.97 60.39,17.11 60.54,17.26 60.68,17.26 60.96,16.98 61.1,16.98 61.24,17.12 61.24,17.27 60.97,17.54 60.97,17.69 61.11,17.83 61.26,17.83 61.53,17.56 61.68,17.56 61.82,17.7 61.82,17.84 61.54,18.12 61.54,18.26 61.69,18.41 61.83,18.41 62.11,18.13 62.25,18.13 62.39,18.27 62.39,18.42 62.12,18.69 62.12,18.84 62.26,18.98 62.41,18.98 62.68,18.71 62.83,18.71 62.97,18.85 62.97,18.99 62.69,19.27 62.69,19.41 62.84,19.56 62.98,19.56 63.26,19.28 63.4,19.28 63.54,19.42 63.54,19.57 63.27,19.84 63.27,19.99 63.41,20.13 63.56,20.13 63.83,19.86 63.98,19.86 64.12,20 64.12,20.14 63.84,20.42 63.84,20.56 63.99,20.71 64.13,20.71 64.41,20.43 64.55,20.43 69.93,25.81 75.97,25.81 80.9,20.88 v1(84.1,20.88) 85.72,22.5 85.72,34.14 83.14,36.73 82.99,36.73 82.69,36.43 82.55,36.43 82.4,36.57 82.4,36.71 82.7,37.01 82.7,37.16 82.56,37.3 82.42,37.3 82.12,37 81.97,37 81.83,37.14 81.83,37.29 82.13,37.59 82.13,37.73 81.99,37.88 81.84,37.88 81.54,37.58 81.4,37.58 81.25,37.72 81.25,37.86 81.55,38.16 81.55,38.31 81.41,38.45 81.27,38.45 80.97,38.15 80.82,38.15 80.68,38.3 80.68,38.44 80.98,38.74 80.98,38.88 80.84,39.03 80.69,39.03 80.39,38.73 80.25,38.73 80.1,38.87 80.1,39.01 80.4,39.31 80.4,39.46 70.56,49.3 v1(69.39,49.3)
BST_LA: length 2.4
  TOP w0.356: U1309.24 47.15,50.61
  TOP w0.508: 47.15,50.61 C1221.2
BST_LB: length 2.4
  TOP w0.356: 47.2,53.86 U1309.19
  TOP w0.508: C1225.2 45.86,53.86 47.2,53.86
BST_RA: length 2.4
  TOP w0.356: 47.2,54.51 U1309.18
  TOP w0.508: 47.2,54.51 45.88,54.51 C1226.2
BST_RB: length 2.4
  TOP w0.356: U1309.13 47.1,57.76
  TOP w0.508: 47.1,57.76 C1231.2
DATA: length 5.5
  TOP w0.102: J813.4 81.68,8.75 81.23,9.2 v1(81.23,11.33) R2972.1
  BOTTOM w0.102: v1(81.23,11.33) DATA.1
LRCK: length 5.1
  TOP w0.102: J813.6 82.68,9.14 82.3,9.52 v1(82.3,11.33) R2970.1
  BOTTOM w0.102: LRCK.1 v1(82.3,11.33)
MCLK: length 3.4
  TOP w0.102: J813.2 v1(80.68,9.47) 80.68,10.13 R2974.1
  BOTTOM w0.102: MCLK.1 v1(80.68,9.47)
MLA: length 9.7
  TOP w0.356: U1309.22 47.31,51.91
  TOP w0.508: 47.31,51.91 46.82,51.42 C1221.1 45.33,51.42 42.96,49.05 C1218.1
MLB: length 6.9
  TOP w0.356: 47.15,53.21 U1309.20
  TOP w0.508: 47.15,53.21 46.58,53.21 46.31,52.94 C1225.1 44.94,52.94 44.23,52.23 C1224.2
MRA: length 6.9
  TOP w0.356: 47.28,55.16 U1309.17
  TOP w0.508: 47.28,55.16 46.53,55.16 46.24,55.45 C1226.1 44.86,55.45 44.2,56.11 C1228.2
MRB: length 9.7
  TOP w0.356: U1309.15 47.27,56.46
  TOP w0.508: C1239.1 42.96,59.29 45.3,56.95 C1231.1 46.78,56.95 47.27,56.46
PD_AD82584F: length 62.3
  TOP w0.102: v1(83.39,25.35) 83.39,23.39 84.81,21.97 84.81,8.84 84.68,8.71 J813.10 ; v1(57.89,43.03) 57.89,48.57 R2888.1
  BOTTOM w0.102: v1(57.89,43.03) PD_AD82584F.1 83.39,32.23 v1(83.39,25.35)
PD_AD83586B: length 54
  TOP w0.102: v1(54.48,16.97) 54.46,16.99 R2984.1 ; v1(84.05,23.85) 85.37,22.53 85.37,9.07 85.68,8.76 J813.12
  BOTTOM w0.102: v1(84.05,23.85) 83.41,23.22 80.34,23.22 75.11,28.45 PD_AD83586B.1 69.65,28.45 58.17,16.97 v1(54.48,16.97)
PWR_3V3: length 9.4
  TOP w0.305: R2886.1 v1(52.84,47.7) ; R2898.2 v1(48.01,19.2) ; R2893.2 54.56,18.83 ; 54.56,18.83 v1(55.27,18.83) ; 54.56,18.83 R2895.2 ; R2927.2 v1(48.35,17.2) ; R2897.2 v1(48.93,19.26) ; R2982.2 v1(52.1,15.06) R2981.2
  TOP w0.356: R2932.2 v1(59.39,53.73) ; L804.1 v1(59.44,55.71) ; R2933.2 v1(59.39,54.67)
  TOP w0.508: L807.1 v1(51.67,16.82) ; L814.1 v1(49.92,36.94)
  vias: v1(52.7,35.69) v1(52.68,35.1) v1(86.94,24.05) v1(86.94,23.5) v1(87.66,24.05) v1(87.66,23.5)
PWR_24V:
  vias: v1(34.54,47.04) v1(34.54,46.41) v1(35.15,47.07) v1(35.15,46.43) v1(35.79,47.09) v1(35.79,46.46) v1(36.7,6.3) v1(36.7,5.66) v1(37.34,6.32) v1(37.34,5.69) v1(37.95,6.35) v1(37.95,5.71) v1(38.13,69.29) v1(38.15,68.66) v1(38.18,68.05) v1(38.76,69.29) v1(38.79,68.66) v1(38.81,68.05) v1(59.39,66.62) v1(59.39,65.99) v1(59.39,65.35) v1(60.02,66.62) v1(60.02,65.99) v1(60.02,65.35) v1(60.66,66.62) v1(60.66,65.99) v1(60.66,65.35) v1(61.29,66.62) v1(61.29,65.99) v1(61.29,65.35) v1(61.87,12.73) v1(61.87,12.09) v1(62.48,12.75) v1(62.48,12.12) v1(63.12,12.78) v1(63.12,12.14)
SAA: length 10.3
  TOP w0.254: U804.15 45.38,28.84
  TOP w0.508: C1272.2 40.39,31.99 40.62,32.22 42.8,32.22 43.34,31.68 43.34,30.88 45.38,28.84
  TOP w0.762: FB7.2 C1272.2
SAB: length 8.8
  TOP w0.254: 44.39,27.84 U804.17
  TOP w0.508: 44.39,27.84 43.44,28.79 40.57,28.79 40.34,29.02 C1269.2
  TOP w0.762: FB6.2 C1269.2
SBA: length 10
  TOP w0.254: 45.53,25.34 U804.22
  TOP w0.508: C1243.1 40.39,22.16 40.62,21.93 42.46,21.93 43.24,22.71 43.24,23.05 45.53,25.34
  TOP w0.762: FB2.2 C1243.1
SBB: length 8.8
  TOP w0.254: 44.45,26.34 U804.20
  TOP w0.508: C1248.1 40.37,25.13 40.6,25.36 43.47,25.36 44.45,26.34
  TOP w0.762: FB3.2 C1248.1
SCL: length 5.8
  TOP w0.102: J813.8 83.68,9.49 83.34,9.83 v1(83.34,11.33) R2977.1
  BOTTOM w0.102: SCL.1 v1(83.34,11.33)
SDA: length 3.1
  TOP w0.102: R2976.1 84.18,9.8 v1(84.18,9.47) J813.9
  BOTTOM w0.102: SDA.1 v1(84.18,9.47)
SLA: length 10.2
  TOP w0.254: 56.39,28.84 U804.46
  TOP w0.508: 56.39,28.84 58.69,31.13 58.69,31.74 59.19,32.25 61.39,32.25 61.62,32.02 C1273.1
  TOP w0.762: FB8.2 C1273.1
SLB: length 8.8
  TOP w0.254: 57.48,27.84 U804.44
  TOP w0.508: C1264.2 61.55,29.05 61.32,28.82 58.45,28.82 57.48,27.84
  TOP w0.762: FB5.2 C1264.2
SRA: length 10.2
  TOP w0.254: U804.39 56.63,25.34
  TOP w0.508: C1242.1 61.53,22.19 61.31,21.96 59.44,21.96 58.93,22.47 58.93,23.04 56.63,25.34
  TOP w0.762: FB1.2 C1242.1
SRB: length 8.8
  TOP w0.254: 57.54,26.34 U804.41
  TOP w0.508: C1255.2 61.59,25.16 61.36,25.39 58.49,25.39 57.54,26.34
  TOP w0.762: FB4.2 C1255.2
N29687767: length 3.2
  TOP w0.356: C1236.2 C1235.1 55.15,57.76 U1309.12
N29687834: length 2.1
  TOP w0.356: U1309.11 55.44,57.11 C1234.1
N29687885: length 4.3
  TOP w0.356: R2816.1 57.72,56.52 C1230.2 C1229.1 55.65,56.46 U1309.10
N29687983: length 4.2
  TOP w0.356: L804.2 C1230.1 C1229.2 55.36,55.71 55.26,55.81 U1309.9
N29689351: length 1.9
  TOP w0.457: C1218.2 40.88,47.68 R2807.1
N29689362: length 1.9
  TOP w0.508: C1224.1 42.83,53.6 R2809.2
N29690216: length 1.9
  TOP w0.457: R2817.1 40.88,60.66 C1239.2
N29690226: length 1.9
  TOP w0.508: R2815.2 42.83,54.74 C1228.1
N29717066: length 4.9
  TOP w0.254: U804.7 50.71,32.96 50.73,32.98
  TOP w0.508: 50.73,32.98 C1274.2 C1275.1 50.73,35.77 R2837.1
N29717079: length 4.2
  TOP w0.254: 49.92,33.05 50.21,32.76 U804.8
  TOP w0.508: L814.2 C1275.2 C1274.1 49.92,33.05
N29719018: length 4.7
  TOP w0.254: U804.30 50.71,21.27 50.97,21.02 C1241.2 C1240.1 50.97,19.07 R2819.1
N29719032: length 4.4
  TOP w0.254: 51.78,20.93 51.21,21.49 U804.31
  TOP w0.508: L807.2 51.78,18.81 C1240.2 C1241.1 51.78,20.93
N29721028: length 1.9
  TOP w0.508: C1242.2 60.69,20.82 R2820.1
N29721038: length 1.9
  TOP w0.508: R2821.2 60.69,26.53 C1255.1
N29721136: length 1.9
  TOP w0.508: C1273.2 60.69,33.39 R2831.1
N29721154: length 1.9
  TOP w0.508: C1264.1 60.69,27.68 R2830.2
N29736891: length 1.9
  TOP w0.508: C1248.2 41.23,26.51 R2823.1
N29736893: length 1.9
  TOP w0.508: C1269.1 41.23,27.65 R2827.2
N29741676: length 1.9
  TOP w0.508: R2822.1 41.23,20.79 C1243.2
N29741678: length 1.9
  TOP w0.508: R2829.2 41.23,33.36 C1272.1
N30395079: length 2.4
  TOP w0.305: 53.78,50.61 U1309.1
  TOP w0.356: 53.78,50.61 R2887.2 R2886.2
N30395618: length 1.8
  TOP w0.102: v1(52.24,21.71) 52.21,21.74 U804.33
  BOTTOM w0.102: ERROR.1 52.15,21.8 v1(52.24,21.71)
N30395650: length 4.9
  TOP w0.254: U804.2 53.21,32.28 53.85,32.92 54.53,32.92 54.91,33.3 54.91,34.57 R2901.2
N30396016: length 5.4
  TOP w0.102: R2983.2 52.17,36.17 51.21,35.21 U804.6
N30396076: length 3.5
  TOP w0.254: R2902.1 53.59,33.58 R2980.2 53.57,33.43 52.71,32.57 U804.3
N30396158: length 2.4
  TOP w0.254: U804.4 52.21,33.09 R2903.1
N30396385: length 2.2
  TOP w0.254: R2904.2 51.71,33.54 U804.5
N30396687: length 2.7
  TOP w0.254: R2898.1 49.21,21.89 U804.27
N30396767: length 2.5
  TOP w0.254: U804.28 49.71,21.47 R2897.1
N30397460: length 4.1
  TOP w0.254: R2893.1 R2929.2 52.71,19.64 C1327.2 U804.34
N30397605: length 2.9
  TOP w0.254: R2905.2 55.49,33.29 53.84,31.64 U804.1
N30398199: length 3.7
  TOP w0.254: U804.36 54.85,22.84 56.14,21.55 R2899.2
N30399203: length 3.8
  TOP w0.254: R2895.1 54.41,19.8 R2894.2 54.41,20.85 53.21,22.05 U804.35
